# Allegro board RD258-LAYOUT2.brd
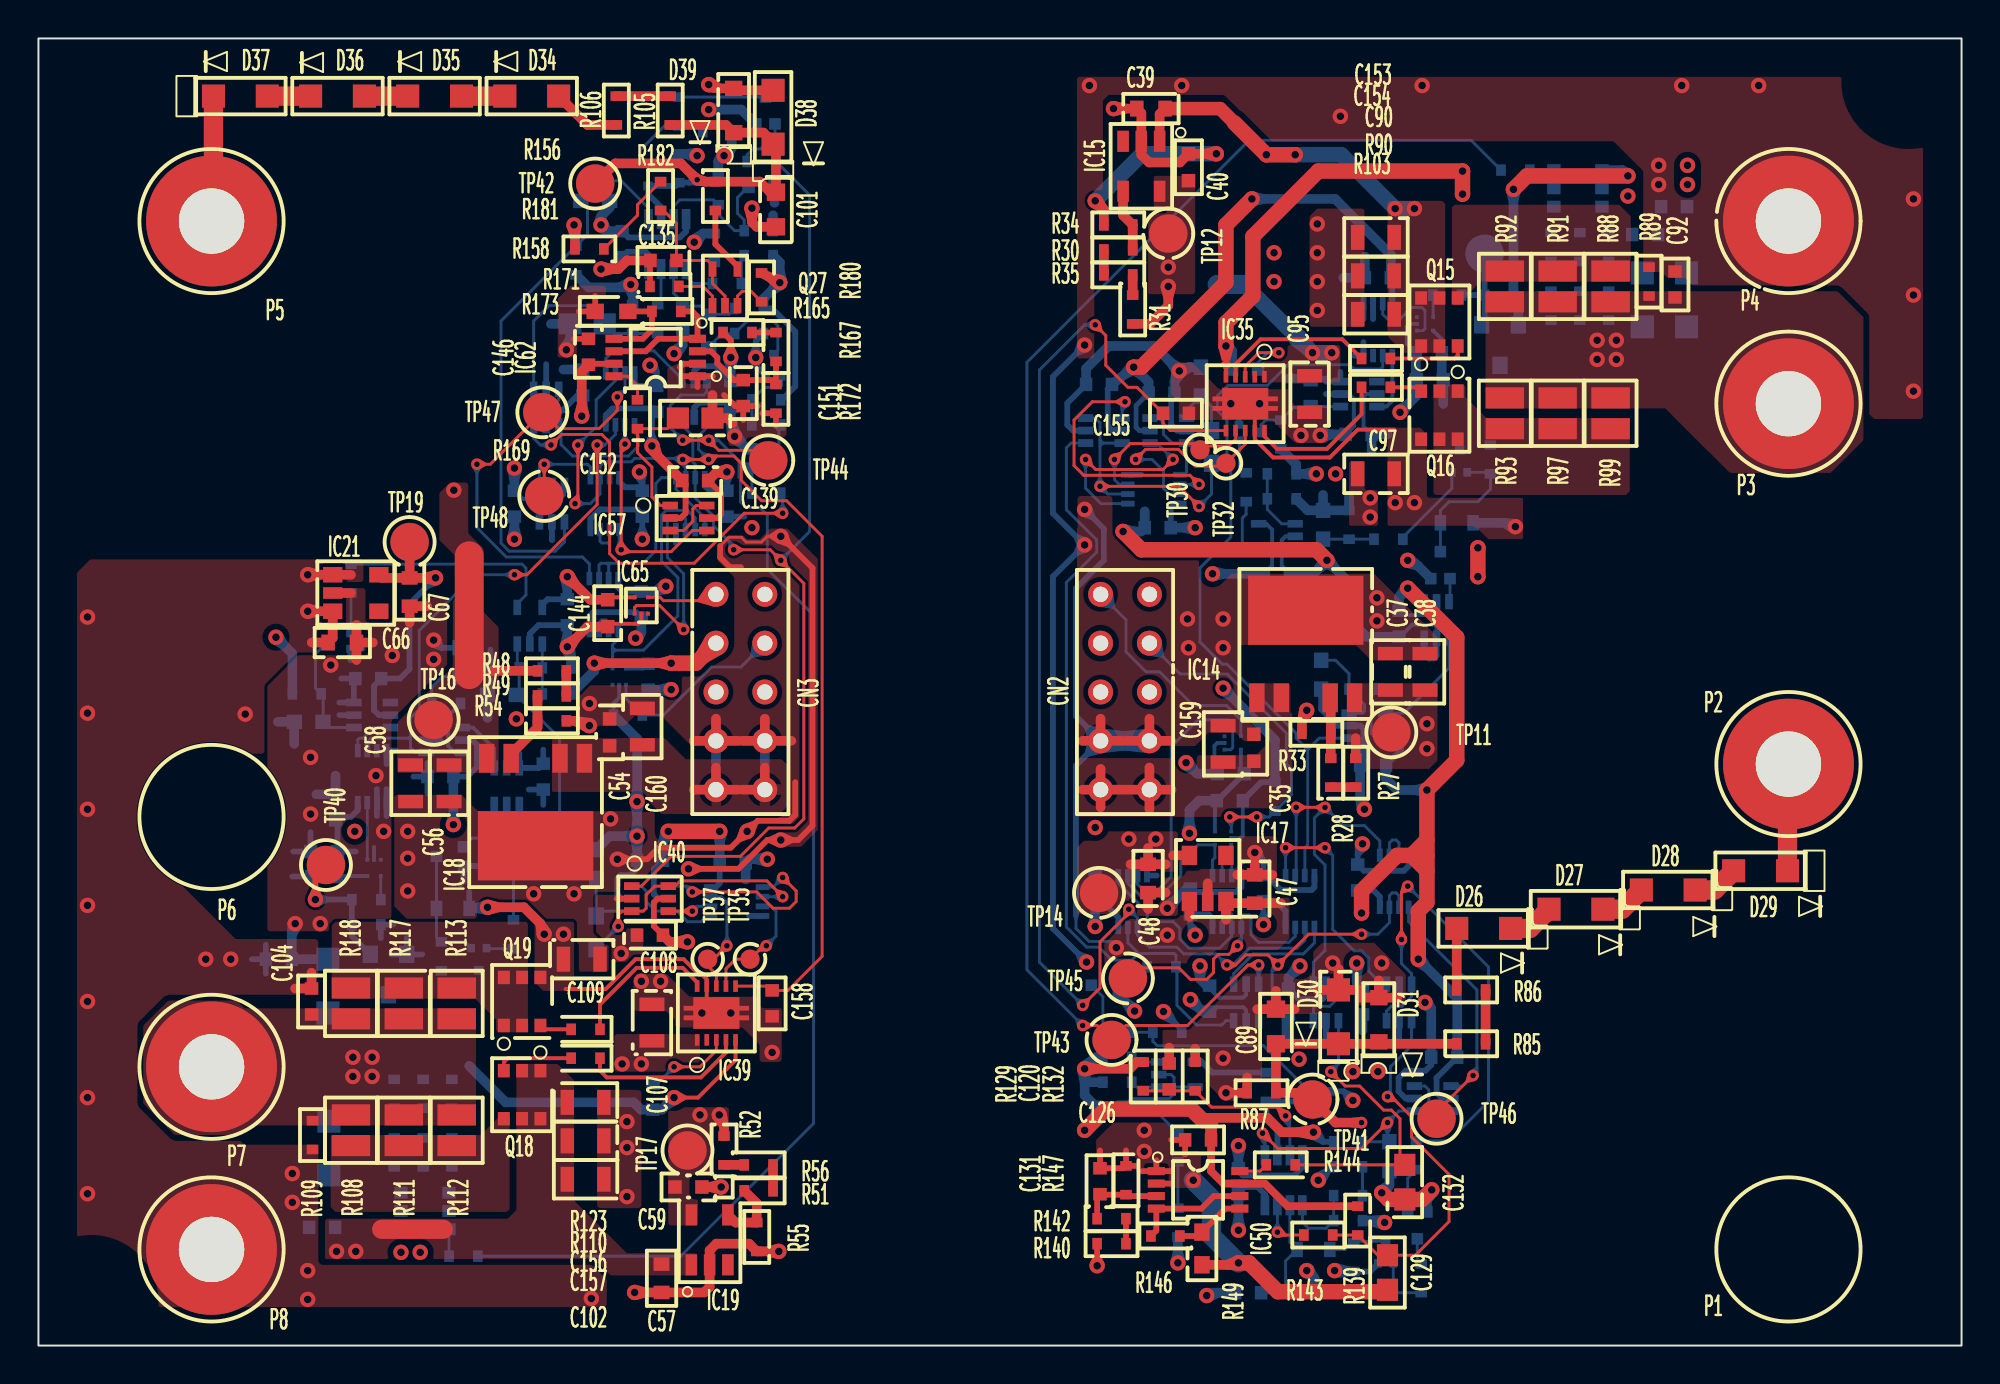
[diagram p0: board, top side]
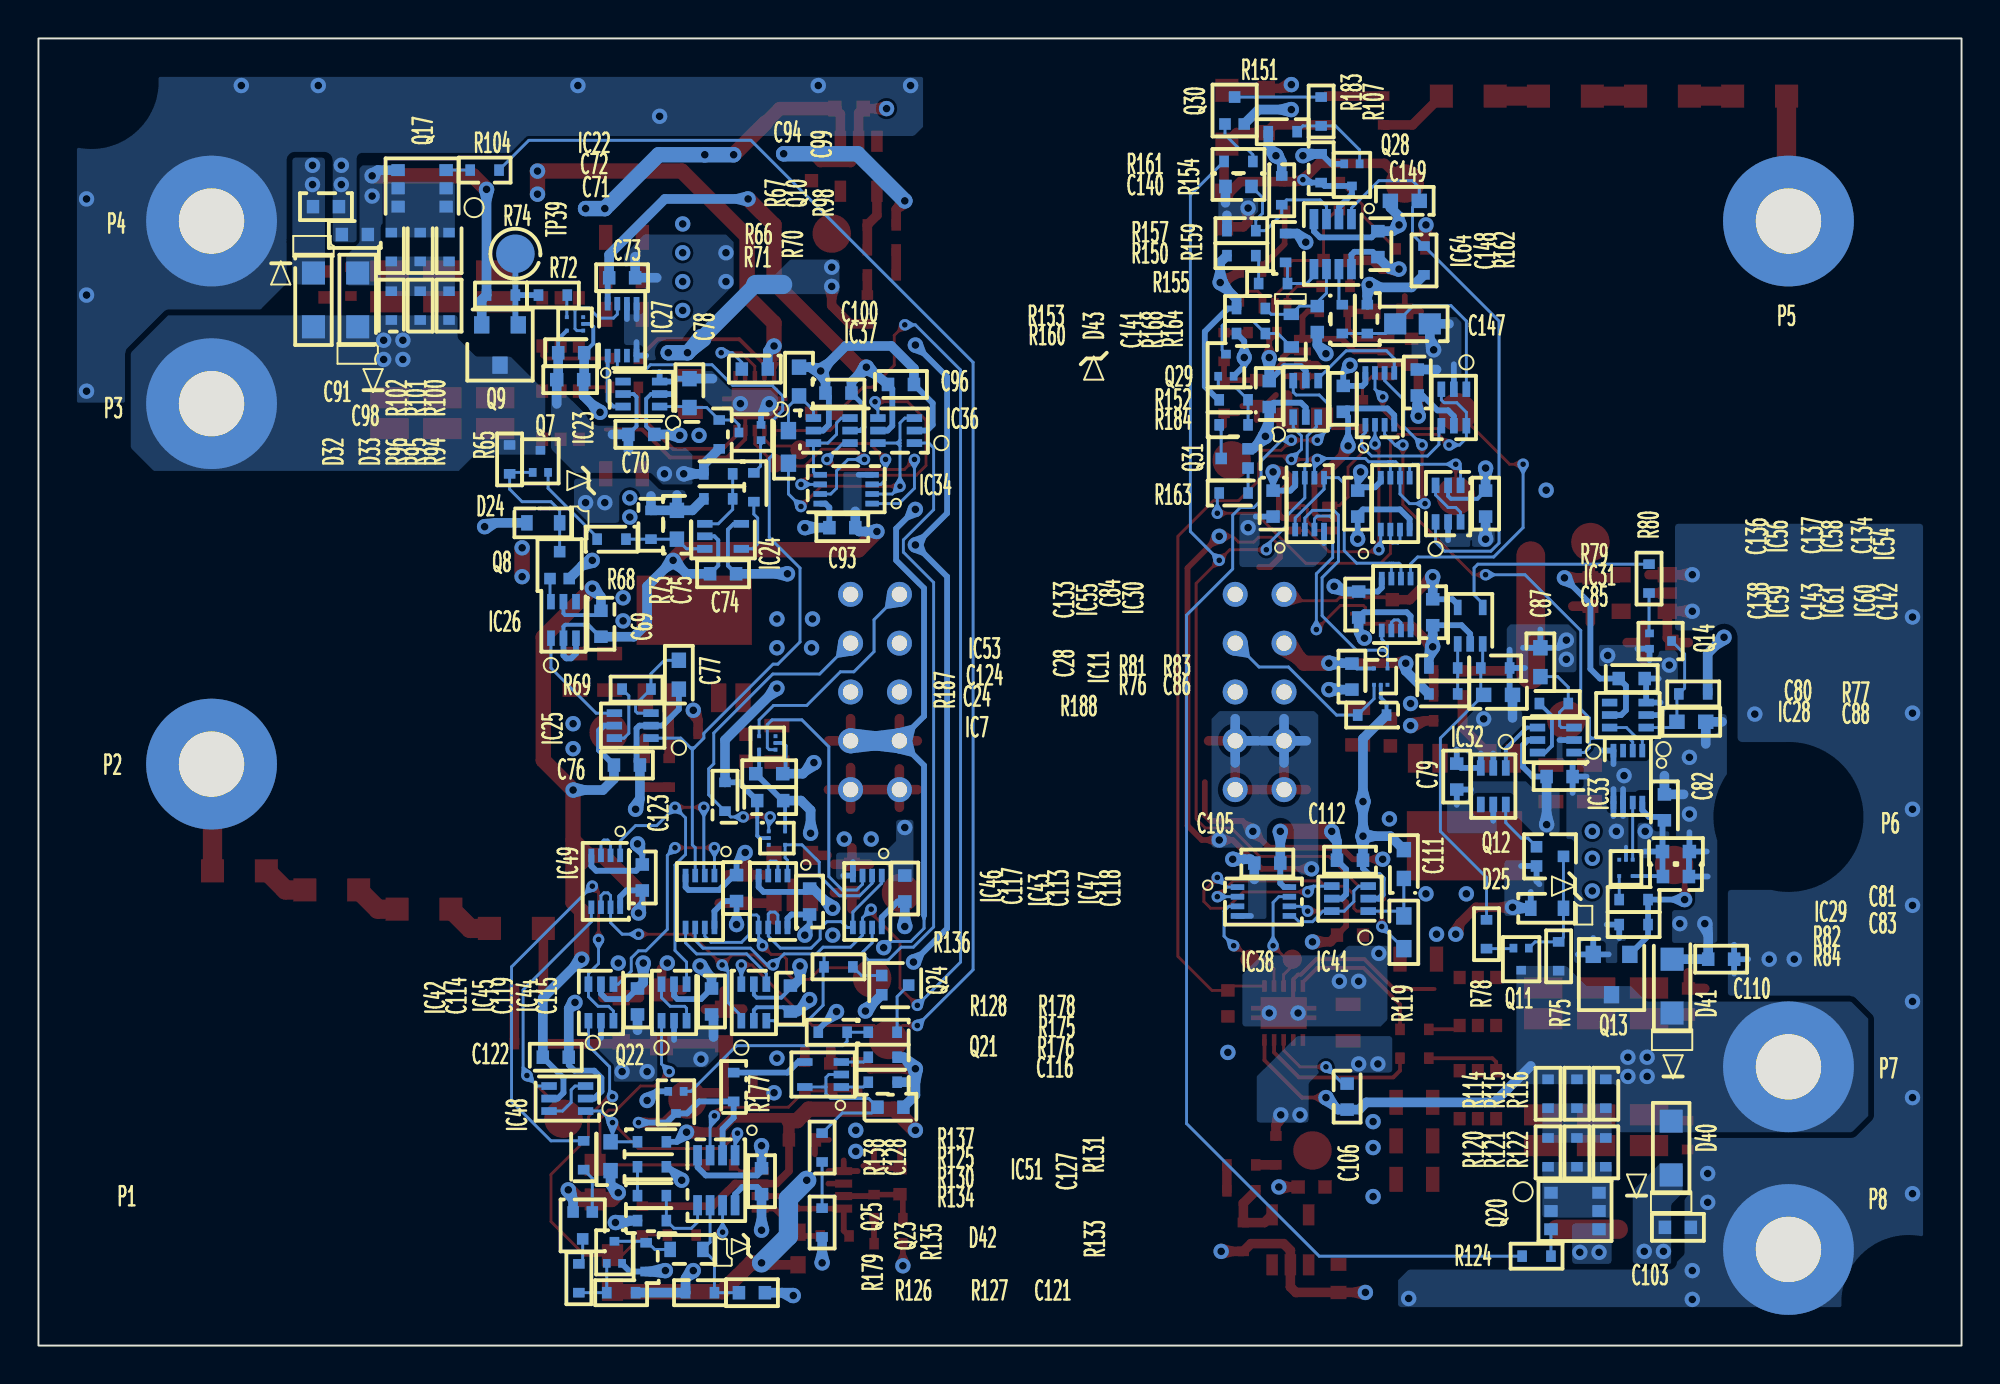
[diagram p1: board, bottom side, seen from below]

Outline 100 x 68 mm; copper layers: TOP, CONDUCTIVE2, CONDUCTIVE3, BOTTOM. Coordinates in mm from the lower left corner of the outline.
Outline path: rectangle 0,0 100,68

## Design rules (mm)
constraint set DEFAULT: 

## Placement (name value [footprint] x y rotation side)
C24  -  [C_CHP_MURATA_L1_6W0_8H0_8A]  61.95 28.35 0 bottom
C28  -  [C_CHP_MURATA_L1_6W0_8H0_8A]  31.7 34.8 270 bottom
C35  -  [C_CHP_TDK_L1_6W0_8H0_8]  63.2 31.1 270 top
C37  -  [C_CHP_MURATA_L2_0W1_25H1_25]  70.3 35.05 270 top
C38  -  [C_CHP_MURATA_L2_0W1_25H1_25]  72.1 35.05 270 top
C39  -  [C_CHP_TYYDN_L1_6W0_8H0_8A]  57.85 64.35 0 top
C40  -  [C_CHP_TDK_L1_6W0_8H0_8]  59.8 61.3 270 top
C47  -  [C_CHP_TYYDN_L1_6W0_8H0_8A]  63.25 23.75 270 top
C48  -  [C_CHP_TYYDN_L1_6W0_8H0_8A]  57.7 24.3 90 top
C54  -  [C_CHP_TDK_L1_6W0_8H0_8]  29.7 31.9 270 top
C56  -  [C_CHP_MURATA_L2_0W1_25H1_25]  21.35 29.25 90 top
C57  -  [C_CHP_TYYDN_L1_6W0_8H0_8A]  32.4 3.5 90 top
C58  -  [C_CHP_MURATA_L2_0W1_25H1_25]  19.35 29.25 90 top
C59  -  [C_CHP_TDK_L1_6W0_8H0_8]  33.8 8.25 180 top
C66  -  [C_CHP_TYYDN_L1_6W0_8H0_8A]  15.8 36.57 180 top
C67  -  [C_CHP_TYYDN_L1_6W0_8H0_8A]  19.3 39.2 90 top
C69  -  [C_CHP_MURATA_L1_6W0_8H0_8A]  70.75 37.55 90 bottom
C70  -  [C_CHP_MURATA_L1_6W0_8H0_8A]  68.65 47.4 0 bottom
C71  -  [C_CHP_TDK_L1_6W0_8H0_8]  72.35 50.25 0 bottom
C72  -  [C_CHP_MURATA_L1_6W0_8H0_8A]  72.3 51.65 0 bottom
C73  -  [C_CHP_MURATA_L1_6W0_8H0_8A]  69.65 55.55 0 bottom
C74  -  [C_CHP_MURATA_L1_6W0_8H0_8A]  64.4 40.15 180 bottom
C75  -  [C_CHP_AVX_L1_6W0_81H0_9]  66.8 42.7 270 bottom
C76  -  [C_CHP_MURATA_L1_6W0_8H0_8A]  69.4 30.2 0 bottom
C77  -  [C_CHP_AVX_L1_6W0_81H0_9]  66.7 34.9 90 bottom
C78  -  [C_CHP_AVX_L1_6W0_81H0_9]  66.15 49.55 270 bottom
C79  -  [C_CHP_MURATA_L1_6W0_8H0_8A]  26.25 29.6 270 bottom
C80  -  [C_CHP_MURATA_L1_6W0_8H0_8A]  17.15 34.7 0 bottom
C81  -  [C_CHP_TDK_L1_6W0_8H0_8]  14.85 25.7 0 bottom
C82  -  [C_CHP_MURATA_L1_6W0_8H0_8A]  15.45 28 270 bottom
C83  -  [C_CHP_MURATA_L1_6W0_8H0_8A]  14.85 24.4 0 bottom
C84  -  [C_CHP_MURATA_L1_6W0_8H0_8A]  27.5 38.15 90 bottom
C85  -  [C_CHP_MURATA_L1_6W0_8H0_8A]  20.9 29.6 0 bottom
C86  -  [C_CHP_AVX_L1_6W0_81H0_9]  24.1 33.85 0 bottom
C87  -  [C_CHP_AVX_L1_6W0_81H0_9]  21.9 35.55 270 bottom
C88  -  [C_CHP_AVX_L1_6W0_81H0_9]  14.05 32.45 0 bottom
C89  -  [C_CHP_AVX_L1_6W0_8H0_9]  64.35 16.6 270 top
C90  -  [C_CHP_MURATA_L2_0W1_25H1_25]  69.55 53.65 0 top
C91  -  [C_CHP_MURATA_L1_6W0_8H0_8A]  85.05 59.25 0 bottom
C92  -  [C_CHP_MURATA_L1_6W0_8H0_8A]  85.1 55.2 90 top
C93  -  [C_CHP_MURATA_L1_6W0_8H0_8A]  58.2 42.55 0 bottom
C94  -  [C_CHP_MURATA_L1_6W0_8H0_8A]  62.75 50.8 0 bottom
C95  -  [C_CHP_MURATA_L2_0W1_25H1_25]  66.1 49.5 90 top
C96  -  [C_CHP_MURATA_L1_6W0_8H0_8A]  55.15 50 0 bottom
C97  -  [C_CHP_MURATA_L2_0W1_25H1_25]  69.55 45.35 180 top
C98  -  [C_CHP_MURATA_L1_6W0_8H0_8A]  83.55 57.8 0 bottom
C99  -  [C_CHP_AVX_L1_6W0_81H0_9]  60.45 50.15 270 bottom
C100  -  [C_CHP_MURATA_L1_6W0_8H0_8A]  58.4 49.55 180 bottom
C101  -  [C_CHP_AVX_L1_6W0_8H0_9]  38.35 59.1 90 top
C102  -  [C_CHP_MURATA_L2_0W1_25H1_25]  28.45 8.65 180 top
C103  -  [C_CHP_MURATA_L1_6W0_8H0_8A]  14.75 6.15 0 bottom
C104  -  [C_CHP_MURATA_L1_6W0_8H0_8A]  14.2 17.9 90 top
C105  -  [C_CHP_MURATA_L1_6W0_8H0_8A]  36.1 25.1 180 bottom
C106  -  [C_CHP_MURATA_L1_6W0_8H0_8A]  31.95 12.95 90 bottom
C107  -  [C_CHP_MURATA_L2_0W1_25H1_25]  31.9 16.8 270 top
C108  -  [C_CHP_MURATA_L1_6W0_8H0_8A]  31.8 21.35 0 top
C109  -  [C_CHP_MURATA_L2_0W1_25H1_25]  28.25 20.1 0 top
C110  -  [C_CHP_MURATA_L1_6W0_8H0_8A]  12.5 20.1 180 bottom
C111  -  [C_CHP_AVX_L1_6W0_81H0_9]  29 25.05 270 bottom
C112  -  [C_CHP_MURATA_L1_6W0_8H0_8A]  31.8 25.25 0 bottom
C113  -  [C_CHP_MURATA_L1_6W0_8H0_8A]  59.9 23.1 270 bottom
C114  -  [C_CHP_MURATA_L1_6W0_8H0_8A]  68.85 17.9 270 bottom
C115  -  [C_CHP_MURATA_L1_6W0_8H0_8A]  60.9 18.05 270 bottom
C116  -  [C_CHP_MURATA_L1_6W0_8H0_8A]  55.7 12.4 180 bottom
C117  -  [C_CHP_MURATA_L1_6W0_8H0_8A]  63.7 23.8 270 bottom
C118  -  [C_CHP_MURATA_L1_6W0_8H0_8A]  54.95 23.77 270 bottom
C119  -  [C_CHP_MURATA_L1_6W0_8H0_8A]  65 17.9 270 bottom
C120  -  [C_CHP_MURATA_L1_6W0_8H0_8A]  58.8 14 270 top
C121  -  [C_CHP_MURATA_L1_6W0_8H0_8A]  62.9 2.75 0 bottom
C122  -  [C_CHP_MURATA_L1_6W0_8H0_8A]  73.1 15 180 bottom
C123  -  [C_CHP_MURATA_L1_6W0_8H0_8A]  68.6 24.35 270 bottom
C124  -  [C_CHP_TDK_L1_6W0_8H0_8]  62 29.75 180 bottom
C126  -  [C_CHP_MURATA_L1_6W0_8H0_8A]  60.3 10.7 0 top
C127  -  [C_CHP_MURATA_L1_6W0_8H0_8A]  62.4 8.55 270 bottom
C128  -  [C_CHP_AVX_L1_6W0_81H0_9]  70.25 9.85 90 bottom
C129  -  [C_CHP_KEMET_L1_6W0_8H0_8]  70.15 3.8 90 top
C131  -  [C_CHP_MURATA_L1_6W0_8H0_8A]  55.2 8.55 270 top
C132  -  [C_CHP_KEMET_L1_6W0_8H0_8]  71.05 8.5 90 top
C133  -  [C_CHP_MURATA_L1_6W0_8H0_8A]  31.35 38.55 90 bottom
C134  -  [C_CHP_MURATA_L1_6W0_8H0_8A]  28.3 50.1 90 bottom
C135  -  [C_CHP_MURATA_L1_6W0_8H0_8A]  32.5 56.45 180 top
C136  -  [C_CHP_MURATA_L1_6W0_8H0_8A]  36 49.5 270 bottom
C137  -  [C_CHP_MURATA_L1_6W0_8H0_8A]  32.15 49.25 90 bottom
C138  -  [C_CHP_MURATA_L1_6W0_8H0_8A]  35.8 43.8 90 bottom
C139  -  [C_CHP_MURATA_L1_6W0_8H0_8A]  34.15 45 180 top
C140  -  [C_CHP_MURATA_L1_6W0_8H0_8A]  37.6 60.3 180 bottom
C141  -  [C_CHP_MURATA_L1_6W0_8H0_8A]  33.5 53.4 90 bottom
C142  -  [C_CHP_MURATA_L1_6W0_8H0_8A]  24.75 43.8 270 bottom
C143  -  [C_CHP_MURATA_L1_6W0_8H0_8A]  31.4 43.8 90 bottom
C144  -  [C_CHP_TDK_L1_6W0_8H0_8]  29.6 38.1 270 top
C146  -  [C_CHP_MURATA_L1_6W0_8H0_8A]  28.6 51.7 270 top
C147  -  [C_CHP_KEMET_L1_6W0_8H0_8]  28.55 53.15 0 bottom
C148  -  [C_CHP_MURATA_L1_6W0_8H0_8A]  30.35 57.3 270 bottom
C149  -  [C_CHP_AVX_L1_6W0_81H0_9]  28.95 59.55 180 bottom
C151  -  [C_CHP_MURATA_L1_6W0_8H0_8A]  36.65 49.55 90 top
C152  -  [C_CHP_KEMET_L1_6W0_8H0_8]  34.15 48.25 180 top
C153  -  [C_CHP_MURATA_L2_0W1_25H1_25]  69.55 57.65 0 top
C154  -  [C_CHP_MURATA_L2_0W1_25H1_25]  69.55 55.65 0 top
C155  -  [C_CHP_MURATA_L1_6W0_8H0_8A]  59.15 48.5 0 top
C156  -  [C_CHP_MURATA_L2_0W1_25H1_25]  28.45 12.65 180 top
C157  -  [C_CHP_MURATA_L2_0W1_25H1_25]  28.45 10.65 180 top
C158  -  [C_CHP_MURATA_L1_6W0_8H0_8A]  38.15 17.8 270 top
C159  -  [C_CHP_MURATA_L2_0W1_25H1_25]  61.6 31.3 270 top
C160  -  [C_CHP_MURATA_L2_0W1_25H1_25]  31.4 32.2 270 top
CN2  -  [PMW_61_5PW]  55.23 28.92 90 top
CN3  -  [PMW_61_5PW]  35.23 28.92 90 top
D24  -  [ZD_SMD_TSB_K_1_A_2_L1_2W0_8H0_6]  73.75 42.8 0 bottom
D25  -  [ZD_SMD_TSB_K_1_A_2_L1_2W0_8H0_6]  21.55 22.75 0 bottom
D26  -  [D_SMD_TSB_K_2_A_1_L2_6W1_6H0_98]  75.15 21.7 180 top
D27  -  [D_SMD_TSB_K_2_A_1_L2_6W1_6H0_98]  79.95 22.7 180 top
D28  -  [D_SMD_TSB_K_2_A_1_L2_6W1_6H0_98]  84.75 23.7 180 top
D29  -  [D_SMD_TSB_K_2_A_1_L2_6W1_6H0_98]  89.55 24.7 180 top
D30  -  [D_SMD_TSB_K_2_A_1_L2_6W1_6H0_98]  67.6 17.1 90 top
D31  -  [D_SMD_TSB_K_2_A_1_L1_7W1_25H0_9]  69.7 16.95 90 top
D32  -  [D_SMD_TSB_K_2_A_1_L2_6W1_6H0_98]  85.7 54.4 270 bottom
D33  -  [D_SMD_TSB_K_2_A_1_L2_6W1_6H0_98]  83.4 54.4 90 bottom
D34  -  [D_SMD_TSB_K_2_A_1_L2_6W1_6H0_98]  25.65 65 0 top
D35  -  [D_SMD_TSB_K_2_A_1_L2_6W1_6H0_98]  20.6 65 0 top
D36  -  [D_SMD_TSB_K_2_A_1_L2_6W1_6H0_98]  15.55 65 0 top
D37  -  [D_SMD_TSB_K_2_A_1_L2_6W1_6H0_98]  10.5 65 0 top
D38  -  [D_SMD_TSB_K_2_A_1_L2_6W1_6H0_98]  38.2 63.9 90 top
D39  -  [D_SMD_TSB_K_2_A_1_L1_7W1_25H0_9]  36.15 64.25 90 top
D40  -  [D_SMD_TSB_K_2_A_1_L2_6W1_6H0_98]  15.1 10.28 90 bottom
D41  -  [D_SMD_TSB_K_2_A_1_L2_6W1_6H0_98]  15.05 18.7 90 bottom
D42  -  [ZD_SMD_TSB_K_1_A_2_L1_2W0_8H0_6]  66.3 5 0 bottom
D43  -  [ZD_SMD_TSB_K_1_A_2_L1_2W0_8H0_6]  34.85 52.8 270 bottom
IC7  -  [IC_SMD_5_TSB_L1_0W0_8H0_48_RCNT]  61.6 26.4 270 bottom
IC11  -  [IC_SMD_5_TSB_L1_0W0_8H0_48_RCNT]  30.2 34.8 180 bottom
IC14  -  [REG_TO_252_5S_A_ABLIC_L6_5W4_7H1_4]  65.9 37 0 top
IC15  -  [IC_SOP_5_TI_L3_05W1_75H1_45]  57.35 61.35 180 top
IC17  -  [IC_SC74A_TSB_L2_9W1_6H1_15_RP0_05]  60.8 24.3 0 top
IC18  -  [REG_TO_252_5S_A_ABLIC_L6_5W4_7H1_4]  25.85 27.25 180 top
IC19  -  [IC_SOP_5_TI_L3_05W1_75H1_45]  34.9 5.5 0 top
IC21  -  [IC_SC74A_TSB_L2_9W1_6H1_15_RP0_05]  16.5 39.15 270 top
IC22  -  [IC_SMD_5_TSB_L1_0W0_8H0_48_RCNT]  72.1 53.15 90 bottom
IC23  -  [IC_SOP_6_TSB_L2_0W1_25H0_95_RP0_05]  68.65 49.5 90 bottom
IC24  -  [IC_SC88A_TSB_L2_0W1_25H0_95_RP0_05]  64.4 42.1 270 bottom
IC25  -  [IC_SOP_6_TSB_L2_0W1_25H0_95_RP0_05]  69.1 32.25 90 bottom
IC26  -  [IC_SOP_6_TSB_L2_0W1_25H0_95_RP0_05]  72.7 37.75 180 bottom
IC27  -  [IC_SOP_8_TSB_L2_0W2_3H0_75_P0_5_RP0_05]  69.65 52.85 180 bottom
IC28  -  [IC_SOP_6_TSB_L2_0W1_25H0_95_RP0_05]  17.35 32.8 90 bottom
IC29  -  [IC_SMD_5_TSB_L1_0W0_8H0_48_RCNT]  17.45 24.85 0 bottom
IC30  -  [IC_SC88A_TSB_L2_0W1_25H0_95_RP0_05]  25.55 37.45 180 bottom
IC31  -  [IC_SOP_6_TSB_L2_0W1_25H0_95_RP0_05]  21.1 31.5 90 bottom
IC32  -  [IC_SOP_6_TSB_L2_0W1_25H0_95_RP0_05]  24.35 29.1 0 bottom
IC33  -  [IC_SOP_8_TSB_L2_0W2_3H0_75_P0_5_RP0_05]  17.35 29.6 0 bottom
IC34  -  [IC_SOP_8_TSB_L2_0W2_3H0_75_P0_5_RP0_05]  58 44.55 90 bottom
IC35  -  [IC_SON_10S1_TI_L3_1W3_1H1_0_RP0_05_2]  62.75 49 180 top
IC36  -  [IC_SOP_6_TSB_L2_0W1_25H0_95_RP0_05]  55.4 47.6 90 bottom
IC37  -  [IC_SOP_6_TSB_L2_0W1_25H0_95_RP0_05]  58.75 47.6 270 bottom
IC38  -  [IC_SOP_8_TSB_L2_0W2_3H0_75_P0_5_RP0_05]  36.3 23.1 270 bottom
IC39  -  [IC_SON_10S1_TI_L3_1W3_1H1_0_RP0_05_2]  35.25 17.3 0 top
IC40  -  [IC_SOP_6_TSB_L2_0W1_25H0_95_RP0_05]  31.8 23.25 270 top
IC41  -  [IC_SOP_6_TSB_L2_0W1_25H0_95_RP0_05]  31.8 23.25 90 bottom
IC42  -  [IC_SOP_6_TSB_L2_0W1_25H0_95_RP0_05]  70.75 17.85 180 bottom
IC43  -  [IC_SOP_8_TSB_L2_0W2_3H0_75_P0_5_RP0_05]  61.8 23.1 0 bottom
IC44  -  [IC_SOP_6_TSB_L2_0W1_25H0_95_RP0_05]  62.8 17.85 180 bottom
IC45  -  [IC_SOP_6_TSB_L2_0W1_25H0_95_RP0_05]  66.95 17.85 180 bottom
IC46  -  [IC_SOP_8_TSB_L2_0W2_3H0_75_P0_5_RP0_05]  65.6 23.1 0 bottom
IC47  -  [IC_SOP_8_TSB_L2_0W2_3H0_75_P0_5_RP0_05]  56.9 23.1 0 bottom
IC48  -  [IC_SOP_6_TSB_L2_0W1_25H0_95_RP0_05]  72.5 12.85 90 bottom
IC49  -  [IC_SOP_8_TSB_L2_0W2_3H0_75_P0_5_RP0_05]  70.5 24.15 0 bottom
IC50  -  [IC_MS8_LINEAR_L3_0W3_0H1_1_P0_65]  60.3 8.1 270 top
IC51  -  [IC_DDF_TI_L2_9W1_6H1_1_P0_65]  64.75 8.6 0 bottom
IC53  -  [IC_SMD_5_TSB_L1_0W0_8H0_48_RCNT]  62.1 31.35 90 bottom
IC54  -  [IC_SOP_6_TSB_L2_0W1_25H0_95_RP0_05]  26.4 48.8 0 bottom
IC55  -  [IC_SOP_8_TSB_L2_0W2_3H0_75_P0_5_RP0_05]  29.4 38.55 180 bottom
IC56  -  [IC_SOP_6_TSB_L2_0W1_25H0_95_RP0_05]  34.1 49.25 180 bottom
IC57  -  [IC_SOP_6_TSB_L2_0W1_25H0_95_RP0_05]  33.8 43.05 270 top
IC58  -  [IC_SOP_8_TSB_L2_0W2_3H0_75_P0_5_RP0_05]  30.25 49.25 180 bottom
IC59  -  [IC_SOP_8_TSB_L2_0W2_3H0_75_P0_5_RP0_05]  33.9 43.8 180 bottom
IC60  -  [IC_SOP_6_TSB_L2_0W1_25H0_95_RP0_05]  26.7 43.8 180 bottom
IC61  -  [IC_SOP_8_TSB_L2_0W2_3H0_75_P0_5_RP0_05]  29.45 43.8 180 bottom
IC62  -  [IC_MS8_LINEAR_L3_0W3_0H1_1_P0_65]  32.1 51.4 90 top
IC64  -  [IC_DDF_TI_L2_9W1_6H1_1_P0_65]  32.7 57.3 0 bottom
IC65  -  [IC_SMD_5_TSB_L1_0W0_8H0_48_RCNT]  31.35 38.5 0 top
NOREF  -  []  91 5 0 top
NOREF#2  -  []  9 27.5 0 top
P2  -  [ITNS_TH3_4_P_C6_8]  91 30.25 0 top
P3  -  [ITNS_TH3_4_P_C6_8]  91 49 0 top
P4  -  [ITNS_TH3_4_P_C6_8]  91 58.5 0 top
P5  -  [ITNS_TH3_4_P_C6_8]  9 58.5 0 top
P7  -  [ITNS_TH3_4_P_C6_8]  9 14.5 0 top
P8  -  [ITNS_TH3_4_P_C6_8]  9 5 0 top
Q7  -  [TR_SMD_3_TSB_B_1_E_2_C_3_L1_2W0_8H0_5]  73.9 46 180 bottom
Q8  -  [FET_SMD_TSB_G_1_S_2_D_3_L1_6W0_8H0_75]  72.9 40.6 180 bottom
Q9  -  [FET_SMD_TSB_L2_9W1_8H0_8]  76 52.05 0 bottom
Q10  -  [TR_SMD_3_TSB_B_1_E_2_C_3_L1_2W0_8H0_5]  63 47.5 90 bottom
Q11  -  [TR_SMD_3_TSB_B_1_E_2_C_3_L1_2W0_8H0_5]  22.9 20.1 0 bottom
Q12  -  [FET_SMD_TSB_G_1_S_2_D_3_L1_6W0_8H0_75]  21.4 25.45 270 bottom
Q13  -  [FET_SMD_TSB_L2_9W1_8H0_8]  18.2 19.3 0 bottom
Q14  -  [TR_SMD_3_TSB_B_1_E_2_C_3_L1_2W0_8H0_5]  15.65 36.65 270 bottom
Q15  -  [FET_SMD_TSB_D_1_2_5_6_G_3_S_4_L2_9W2_2H0_8_RP0_05]  72.85 53.25 0 top
Q16  -  [FET_SMD_TSB_D_1_2_5_6_G_3_S_4_L2_9W2_2H0_8_RP0_05]  72.85 48.4 180 top
Q17  -  [FET_SMD_TSB_D_1_2_5_6_G_3_S_4_L2_9W2_2H0_8_RP0_05]  80.05 60.2 90 bottom
Q18  -  [FET_SMD_TSB_D_1_2_5_6_G_3_S_4_L2_9W2_2H0_8_RP0_05]  25.15 13.05 180 top
Q19  -  [FET_SMD_TSB_D_1_2_5_6_G_3_S_4_L2_9W2_2H0_8_RP0_05]  25.15 17.9 0 top
Q20  -  [FET_SMD_TSB_D_1_2_5_6_G_3_S_4_L2_9W2_2H0_8_RP0_05]  20.1 7 270 bottom
Q21  -  [TR_USV_TSB_L2_0W1_25H1_1]  59.2 14.1 90 bottom
Q22  -  [TR_SMD_3_TSB_B_1_E_2_C_3_L1_2W0_8H0_5]  66.85 12.65 0 bottom
Q23  -  [TR_SMD_3_TSB_B_1_E_2_C_3_L1_2W0_8H0_5]  70.05 4.85 180 bottom
Q24  -  [FET_SMD_TSB_G_1_S_2_D_3_L1_6W0_8H0_75]  55.45 18.75 270 bottom
Q25  -  [FET_SMD_TSB_G_1_S_2_D_3_L1_6W0_8H0_75]  71.7 6.25 0 bottom
Q27  -  [TR_USV_TSB_L2_0W1_25H1_1]  35.7 55.05 0 top
Q28  -  [TR_SMD_3_TSB_B_1_E_2_C_3_L1_2W0_8H0_5]  31.7 60.9 0 bottom
Q29  -  [TR_SMD_3_TSB_B_1_E_2_C_3_L1_2W0_8H0_5]  38.25 51 180 bottom
Q30  -  [FET_SMD_TSB_G_1_S_2_D_3_L1_6W0_8H0_75]  37.8 64.25 180 bottom
Q31  -  [FET_SMD_TSB_G_1_S_2_D_3_L1_6W0_8H0_75]  37.8 46.15 90 bottom
R27  -  [R_CHP_KOA_L1_6W0_8H0_45]  68.5 29.8 90 top
R28  -  [R_CHP_KOA_L1_6W0_8H0_45]  67.2 29.8 270 top
R30  -  [R_CHP_KOA_L1_6W0_8H0_45]  56.15 57 180 top
R31  -  [R_CHP_KOA_L1_6W0_8H0_45]  56.9 53.9 270 top
R33  -  [R_CHP_KOA_L1_6W0_8H0_45]  66.45 31.85 0 top
R34  -  [R_CHP_KOA_L1_6W0_8H0_45]  56.15 58.3 0 top
R35  -  [R_CHP_KOA_L1_6W0_8H0_45]  56.15 55.7 0 top
R48  -  [R_CHP_KOA_L1_6W0_8H0_45]  26.7 35.1 180 top
R49  -  [R_CHP_KOA_L1_6W0_8H0_45]  26.7 33.8 0 top
R51  -  [R_CHP_KOA_L1_6W0_8H0_45]  37.45 8.05 0 top
R52  -  [R_CHP_KOA_L1_6W0_8H0_45]  35.65 10.15 90 top
R54  -  [R_CHP_KOA_L1_6W0_8H0_45]  26.7 32.5 180 top
R55  -  [R_CHP_KOA_L1_6W0_8H0_45]  37.35 5.65 90 top
R56  -  [R_CHP_KOA_L1_6W0_8H0_45]  37.45 9.4 180 top
R65  -  [R_CHP_KOA_L1_6W0_8H0_45]  75.5 46.1 90 bottom
R66  -  [R_CHP_KOA_L1_6W0_8H0_45]  64.65 45.35 0 bottom
R67  -  [R_CHP_KOA_L1_6W0_8H0_45]  64.6 47.4 270 bottom
R68  -  [R_CHP_KOA_L1_6W0_8H0_45]  70.2 41.95 0 bottom
R69  -  [R_CHP_KOA_L1_6W0_8H0_45]  68.9 34.15 180 bottom
R70  -  [R_CHP_KOA_L1_6W0_8H0_45]  62.8 44.65 270 bottom
R71  -  [R_CHP_KOA_L1_6W0_8H0_45]  64.65 44.05 180 bottom
R72  -  [R_CHP_KOA_L1_6W0_8H0_45]  73.25 54.65 0 bottom
R73  -  [R_CHP_KOA_L1_6W0_8H0_45]  68.15 42.7 270 bottom
R74  -  [R_CHP_KOA_L1_6W0_8H0_45]  75.95 54.65 180 bottom
R75  -  [R_CHP_KOA_L1_6W0_8H0_45]  20.95 20.25 270 bottom
R76  -  [R_CHP_KOA_L1_6W0_8H0_45]  26.95 33.9 0 bottom
R77  -  [R_CHP_KOA_L1_6W0_8H0_45]  13.95 33.9 180 bottom
R78  -  [R_CHP_KOA_L1_6W0_8H0_45]  24.7 21.4 270 bottom
R79  -  [R_CHP_KOA_L1_6W0_8H0_45]  21.2 33.4 180 bottom
R80  -  [R_CHP_KOA_L1_6W0_8H0_45]  16.25 39.9 90 bottom
R81  -  [R_CHP_KOA_L1_6W0_8H0_45]  26.95 35.25 180 bottom
R82  -  [R_CHP_KOA_L1_6W0_8H0_45]  17.05 23.2 180 bottom
R83  -  [R_CHP_KOA_L1_6W0_8H0_45]  24.25 35.25 0 bottom
R84  -  [R_CHP_KOA_L1_6W0_8H0_45]  17.05 21.9 180 bottom
R85  -  [R_CHP_KOA_L1_6W0_8H0_45]  74.5 15.7 0 top
R86  -  [R_CHP_KOA_L1_6W0_8H0_45]  74.5 18.5 180 top
R87  -  [R_CHP_KOA_L1_6W0_8H0_45]  63.6 13.15 0 top
R88  -  [R_CHP_ROHM_L2_0W1_2H0_55]  81.75 55.1 180 top
R89  -  [R_CHP_KOA_L1_6W0_8H0_45]  83.75 55.35 90 top
R90  -  [R_CHP_KOA_L1_6W0_8H0_45]  69.55 51.35 0 top
R91  -  [R_CHP_ROHM_L2_0W1_2H0_55]  79 55.1 180 top
R92  -  [R_CHP_ROHM_L2_0W1_2H0_55]  76.25 55.1 180 top
R93  -  [R_CHP_ROHM_L2_0W1_2H0_55]  76.25 48.5 0 top
R94  -  [R_CHP_KOA_L1_6W0_8H0_45]  78.65 54.1 270 bottom
R95  -  [R_CHP_KOA_L1_6W0_8H0_45]  80.15 54.1 270 bottom
R96  -  [R_CHP_KOA_L1_6W0_8H0_45]  81.65 54.1 270 bottom
R97  -  [R_CHP_ROHM_L2_0W1_2H0_55]  79 48.5 0 top
R98  -  [R_CHP_YAGEO_L1_6W0_8H0_45]  61 46.75 90 bottom
R99  -  [R_CHP_ROHM_L2_0W1_2H0_55]  81.75 48.5 0 top
R100  -  [R_CHP_KOA_L1_6W0_8H0_45]  78.65 57.15 270 bottom
R101  -  [R_CHP_KOA_L1_6W0_8H0_45]  80.15 57.15 270 bottom
R102  -  [R_CHP_KOA_L1_6W0_8H0_45]  81.65 57.15 270 bottom
R103  -  [R_CHP_KOA_L1_6W0_8H0_45]  69.55 49.85 0 top
R104  -  [R_CHP_KOA_L1_6W0_8H0_45]  76.8 61.15 0 bottom
R105  -  [R_CHP_KOA_L1_6W0_8H0_45]  32.85 64.25 90 top
R106  -  [R_CHP_KOA_L1_6W0_8H0_45]  30.05 64.25 270 top
R107  -  [R_CHP_KOA_L1_6W0_8H0_45]  33.3 61.25 270 bottom
R108  -  [R_CHP_ROHM_L2_0W1_2H0_55]  16.25 11.2 0 top
R109  -  [R_CHP_KOA_L1_6W0_8H0_45]  14.25 10.95 270 top
R110  -  [R_CHP_KOA_L1_6W0_8H0_45]  28.45 14.95 180 top
R111  -  [R_CHP_ROHM_L2_0W1_2H0_55]  19 11.2 0 top
R112  -  [R_CHP_ROHM_L2_0W1_2H0_55]  21.75 11.2 0 top
R113  -  [R_CHP_ROHM_L2_0W1_2H0_55]  21.75 17.8 180 top
R114  -  [R_CHP_KOA_L1_6W0_8H0_45]  21.5 13.1 90 bottom
R115  -  [R_CHP_KOA_L1_6W0_8H0_45]  20 13.1 90 bottom
R116  -  [R_CHP_KOA_L1_6W0_8H0_45]  18.5 13.1 90 bottom
R117  -  [R_CHP_ROHM_L2_0W1_2H0_55]  19 17.8 180 top
R118  -  [R_CHP_ROHM_L2_0W1_2H0_55]  16.25 17.8 180 top
R119  -  [R_CHP_YAGEO_L1_6W0_8H0_45]  29 21.5 90 bottom
R120  -  [R_CHP_KOA_L1_6W0_8H0_45]  21.5 10.05 90 bottom
R121  -  [R_CHP_KOA_L1_6W0_8H0_45]  20 10.05 90 bottom
R122  -  [R_CHP_KOA_L1_6W0_8H0_45]  18.5 10.05 90 bottom
R123  -  [R_CHP_KOA_L1_6W0_8H0_45]  28.45 16.45 180 top
R124  -  [R_CHP_KOA_L1_6W0_8H0_45]  22.1 4.65 180 bottom
R125  -  [R_CHP_KOA_L1_6W0_8H0_45]  68.1 9.3 180 bottom
R126  -  [R_CHP_KOA_L1_6W0_8H0_45]  69.7 2.75 180 bottom
R127  -  [R_CHP_KOA_L1_6W0_8H0_45]  65.6 2.75 0 bottom
R128  -  [R_CHP_KOA_L1_6W0_8H0_45]  58.7 16.3 0 bottom
R129  -  [R_CHP_KOA_L1_6W0_8H0_45]  57.45 14 90 top
R130  -  [R_CHP_KOA_L1_6W0_8H0_45]  68.1 7.8 0 bottom
R131  -  [R_CHP_KOA_L1_6W0_8H0_45]  59.25 10.3 90 bottom
R132  -  [R_CHP_KOA_L1_6W0_8H0_45]  60.15 14 270 top
R133  -  [R_CHP_KOA_L1_6W0_8H0_45]  59.25 6.4 90 bottom
R134  -  [R_CHP_KOA_L1_6W0_8H0_45]  68.1 6.5 180 bottom
R135  -  [R_CHP_KOA_L1_6W0_8H0_45]  68.4 4.6 90 bottom
R136  -  [R_CHP_KOA_L1_6W0_8H0_45]  58.4 19.7 0 bottom
R137  -  [R_CHP_KOA_L1_6W0_8H0_45]  68.1 10.6 180 bottom
R138  -  [R_CHP_KOA_L1_6W0_8H0_45]  71.65 9.9 90 bottom
R139  -  [R_CHP_KOA_L1_6W0_8H0_45]  68.6 6.5 90 top
R140  -  [R_CHP_KOA_L1_6W0_8H0_45]  55.8 5.3 180 top
R142  -  [R_CHP_KOA_L1_6W0_8H0_45]  55.8 6.6 0 top
R143  -  [R_CHP_KOA_L1_6W0_8H0_45]  66.55 5.75 180 top
R144  -  [R_CHP_KOA_L1_6W0_8H0_45]  64.6 9.4 180 top
R146  -  [R_CHP_KOA_L1_6W0_8H0_45]  58.6 5.7 180 top
R147  -  [R_CHP_KOA_L1_6W0_8H0_45]  56.55 8.6 270 top
R149  -  [R_CHP_YAGEO_L1_6W0_8H0_45]  60.5 5.05 90 top
R150  -  [R_CHP_KOA_L1_6W0_8H0_45]  37.45 56.7 0 bottom
R151  -  [R_CHP_KOA_L1_6W0_8H0_45]  35.3 63.15 0 bottom
R152  -  [R_CHP_KOA_L1_6W0_8H0_45]  37.85 49.2 0 bottom
R153  -  [R_CHP_KOA_L1_6W0_8H0_45]  36.95 53.95 0 bottom
R154  -  [R_CHP_KOA_L1_6W0_8H0_45]  35.35 60.1 90 bottom
R155  -  [R_CHP_KOA_L1_6W0_8H0_45]  35.8 55.25 0 bottom
R156  -  [R_CHP_KOA_L1_6W0_8H0_45]  32.35 59.8 270 top
R157  -  [R_CHP_KOA_L1_6W0_8H0_45]  37.45 58 180 bottom
R158  -  [R_CHP_KOA_L1_6W0_8H0_45]  28.65 57.05 0 top
R159  -  [R_CHP_KOA_L1_6W0_8H0_45]  35.15 57.1 270 bottom
R160  -  [R_CHP_KOA_L1_6W0_8H0_45]  36.95 52.65 180 bottom
R161  -  [R_CHP_KOA_L1_6W0_8H0_45]  37.6 61.6 0 bottom
R162  -  [R_CHP_KOA_L1_6W0_8H0_45]  27.95 56.45 270 bottom
R163  -  [R_CHP_KOA_L1_6W0_8H0_45]  37.85 44.35 0 bottom
R164  -  [R_CHP_KOA_L1_6W0_8H0_45]  30.9 53.4 90 bottom
R165  -  [R_CHP_KOA_L1_6W0_8H0_45]  36.35 52.7 180 top
R167  -  [R_CHP_KOA_L1_6W0_8H0_45]  38.35 51.95 90 top
R168  -  [R_CHP_KOA_L1_6W0_8H0_45]  32.2 53.4 90 bottom
R169  -  [R_CHP_KOA_L1_6W0_8H0_45]  31.15 48.45 90 top
R171  -  [R_CHP_KOA_L1_6W0_8H0_45]  32.65 53.8 0 top
R172  -  [R_CHP_KOA_L1_6W0_8H0_45]  38.35 49.25 90 top
R173  -  [R_CHP_YAGEO_L1_6W0_8H0_45]  29.8 53.8 0 top
R175  -  [R_CHP_KOA_L1_6W0_8H0_45]  56.1 15 180 bottom
R176  -  [R_CHP_KOA_L1_6W0_8H0_45]  56.1 13.7 180 bottom
R177  -  [R_CHP_KOA_L1_6W0_8H0_45]  63.85 13.45 90 bottom
R178  -  [R_CHP_KOA_L1_6W0_8H0_45]  56.1 16.3 0 bottom
R179  -  [R_CHP_KOA_L1_6W0_8H0_45]  71.9 3.5 270 bottom
R180  -  [R_CHP_KOA_L1_6W0_8H0_45]  37.6 55.05 90 top
R181  -  [R_CHP_KOA_L1_6W0_8H0_45]  32.55 55.1 180 top
R182  -  [R_CHP_KOA_L1_6W0_8H0_45]  35.2 59.8 270 top
R183  -  [R_CHP_KOA_L1_6W0_8H0_45]  33.3 64.2 270 bottom
R184  -  [R_CHP_KOA_L1_6W0_8H0_45]  37.85 47.9 180 bottom
R187  -  [R_CHP_KOA_L1_6W0_8H0_45]  64.3 28.55 270 bottom
R188  -  [R_CHP_KOA_L1_6W0_8H0_45]  30.65 32.8 0 bottom
TP11  -  [TPAD_P_C2_0_RP0_05_MN]  70.35 31.9 0 top
TP12  -  [TPAD_P_C2_0_RP0_05_MN]  58.75 57.85 0 top
TP14  -  [TPAD_P_C2_0_RP0_05_MN]  55.15 23.55 270 top
TP16  -  [TPAD_P_C2_0_RP0_05_MN]  20.55 32.55 0 top
TP17  -  [TPAD_P_C2_0_RP0_05_MN]  33.75 10.15 270 top
TP19  -  [TPAD_P_C2_0_RP0_05_MN]  19.3 41.8 90 top
TP30  -  [TPAD_P_C1_0_RP0_05_MN]  60.4 46.6 180 top
TP32  -  [TPAD_P_C1_0_RP0_05_MN]  61.75 45.9 180 top
TP35  -  [TPAD_P_C1_0_RP0_05_MN]  37 20.1 270 top
TP37  -  [TPAD_P_C1_0_RP0_05_MN]  34.8 20.1 270 top
TP39  -  [TPAD_P_C2_0_RP0_05_MN]  75.2 56.8 180 bottom
TP40  -  [TPAD_P_C2_0_RP0_05_MN]  14.95 25 180 top
TP41  -  [TPAD_P_C2_0_RP0_05_MN]  66.25 12.8 0 top
TP42  -  [TPAD_P_C2_0_RP0_05_MN]  28.95 60.45 0 top
TP43  -  [TPAD_P_C2_0_RP0_05_MN]  55.8 15.9 0 top
TP44  -  [TPAD_P_C2_0_RP0_05_MN]  37.95 46.05 0 top
TP45  -  [TPAD_P_C2_0_RP0_05_MN]  56.65 19.1 0 top
TP46  -  [TPAD_P_C2_0_RP0_05_MN]  72.7 11.8 0 top
TP47  -  [TPAD_P_C2_0_RP0_05_MN]  26.2 48.55 0 top
TP48  -  [TPAD_P_C2_0_RP0_05_MN]  26.3 44.2 0 top

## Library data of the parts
C24 C28 C69 C70 C72-C74 C76 C79 C80 C82-C85 C91-C94 C96 C98 C100 C103-C106 C108 C110 C112-C115 C117-C119 C122 C123 C126 C127 C133 C134 C136-C139 C142 C143 C146 C148 = GCJ188R71H104KA12D
C35 C40 C54 C59 C71 C81 C124 C144 = C1608X5R1H105K080DB
C37 C38 C56 C58 C95 C107 C159 C160 = GRM21BZ71H475KE15L
C39 C47 C48 C57 C66 C67 = MSASU168SB7474KTNB25
C75 C77 C78 C86-C88 = 06035C680KAT2A
C89 C101 = KGM15ACG2A121KT: alternate symbols: (C89_C_CHP_AVX_L1_6W0_8H0_9,C101_C_CHP_AVX_L1_6W0_8H0_9)
C90 C97 C102 C109 C153 C154 C156 C157 = GRM21BR61H106KE43L
C99 C111 = 06035A200KAT2A
C116 C120 C121 C131 C135 C140 C141 C151 = GCD188R71H103KA01D
C128 C149 = 06035C100KAT2A
C129 C132 C147 C152 = C0603C102K5RACTU
C155 C158 = GCM188R71H102KA37D
CN2 CN3 = PMW-61-5PW: alternate symbols: (CN2_PMW_61_5PW,CN3_PMW_61_5PW)
D24 D25 D42 D43 = CEZ5V6,L3F
D26-D29 D34-D37 = CRF03A,LQ(M
D30 D38 = CRZ10(T5L,TEM,Q)
D31 D39 = CUS05F30,H3F(T
D32 D33 D40 D41 = CRS04(TE85L,Q,M)
IC7 IC11 IC22 IC29 IC53 IC65 = TC7SZ04AFS,L3J
IC14 IC18 = S1213B00HV5T2U7
IC15 IC19 = TLV709A01DBVR
IC17 IC21 = TCR1HF50B,LM(CT
IC23 IC25 IC26 IC28 IC31 IC32 IC36 IC37 IC40-IC42 IC44 IC45 IC48 IC54 IC56 IC57 IC60 = TC7PZ14FU,LJ(CT
IC24 IC30 = TC75S57FU(TE85L,F)
IC27 IC33 IC43 IC49 IC55 IC61 = TC7WZ00FK,LJ(CT
IC34 IC38 IC46 IC47 IC58 IC59 = TC7WZ08FK,LJ(CT
IC35 IC39 = UCC27301ADRCR
IC50 IC62 = LTC1440IMS8
IC51 IC64 = LM393BIDDFR
P2-P5 P7 P8 = ITNS-TH3.4-P_C6.8
Q7 Q10 Q11 Q14 Q22 Q23 Q28 Q29 = 2SC5658T2LR
Q8 Q12 Q24 Q25 Q30 Q31 = SSM3K15AFS,LF(T
Q9 Q13 = SSM3K318R,LF(T
Q15-Q20 = SSM6K804R,LF
Q21 Q27 = HN4A56JU
R27 R48 = RK73H1JTTD2003F
R28 R49 = RK73H1JTTD2001F
R30 R34 R51 R55 = RK73H1JTTD1004F
R31 R52 = RK73H1JTTD4704F
R33 R54 = RK73H1JTTD2002F
R35 R56 = RK73H1JTTD3304F
R65 R73-R75 R83 R84 R89 R109 = RK73B1JTTD103J
R66 R69 R71 R76 R79 R81 = RK73B1JTTD512J
R67 R70 R77 R80 = RK73B1JTTD473J
R68 R78 = RK73B1JTTD471J
R72 R82 R94-R96 R100-R102 R114-R116 R120-R122 = RK73B1JTTD100J
R85 R105 = RK73H1JTTD2200F: alternate symbols: (R105_R_CHP_KOA_L1_6W0_8H0_45,R85_R_CHP_KOA_L1_6W0_8H0_45)
R86 R106 = RK73H1JTTD1101F: alternate symbols: (R106_R_CHP_KOA_L1_6W0_8H0_45,R86_R_CHP_KOA_L1_6W0_8H0_45)
R87 R90 R103 R107 R110 R123 R177 R182 = RK73Z1JTTD: alternate symbols: (T:R_CHP_KOA_L1_6W0_8H0_45,R182_R_CHP_KOA_L1_6W0_8H0_45;B:R_CHP_KOA_L1_6W0_8H0_45,R177_R_CHP_KOA_L1_6W0_8H0_45)
R88 R91 R92 R108 R111 R112 = LTR10EZPF4R70
R93 R97 R99 R113 R117 R118 = LTR10EZPF11R0
R98 R119 = RT0603BRC07500RL
R104 R124 = RK73H1JTTD20R0F
R125 R150 = RK73H1JTTD4302F
R126 R128 R137 R139 R151 R152 R162 R164 = RK73B1JTTD303J
R127 R153 R187 R188 = RK73H1JTTD1003F
R129 R154 = RK73H1JTTD8201F
R130 R155 = RK73H1JTTD2201F
R131 R136 R138 R143 R156 R161 R163 R168 R178 R179 R183 R184 = RK73H1JTTD1001F: alternate symbols: (T:R_CHP_KOA_L1_6W0_8H0_45,R156_R_CHP_KOA_L1_6W0_8H0_45;B:R_CHP_KOA_L1_6W0_8H0_45,R131_R_CHP_KOA_L1_6W0_8H0_45)
R132 R157 = RK73H1JTTD1202F
R133 R158 = RK73H1JTTD1002F: alternate symbols: (T:R_CHP_KOA_L1_6W0_8H0_45,R158_R_CHP_KOA_L1_6W0_8H0_45;B:R_CHP_KOA_L1_6W0_8H0_45,R133_R_CHP_KOA_L1_6W0_8H0_45)
R134 R140 R159 R165 = RK73H1JTTD2702F
R135 R160 = RK73H1JTTD3301F
R142 R167 = RK73H1JTTD3001F
R144 R169 = RK73B1JTTD472J
R146 R171 = RK73H1JTTD1502F
R147 R172 = RK73H1JTTD1802F
R149 R173 = RC0603FR-072M4L
R175 R176 R180 R181 = RK73B1JTTD221J
TP11 TP12 TP14 TP16 TP17 TP19 TP39-TP48 = TPAD-P_C2.0-RP0.05-MN
TP30 TP32 TP35 TP37 = TPAD-P_C1.0-RP0.05-MN

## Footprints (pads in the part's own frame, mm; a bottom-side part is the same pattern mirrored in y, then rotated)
C_CHP_AVX_L1_6W0_8H0_9
  rect 0.9x0.95 smd: 1(-0.9,0) 2(0.9,0)
C_CHP_AVX_L1_6W0_81H0_9
  rect 0.8x0.75 smd: 1(-0.75,0) 2(0.75,0)
C_CHP_KEMET_L1_6W0_8H0_8
  rect 1.15x1.1 smd: 1(-0.9,0) 2(0.9,0)
C_CHP_MURATA_L1_6W0_8H0_8A
  rect 0.65x0.7 smd: 1(-0.675,0) 2(0.675,0)
C_CHP_MURATA_L2_0W1_25H1_25
  rect 0.7x1.3 smd: 1(-0.95,0) 2(0.95,0)
C_CHP_TDK_L1_6W0_8H0_8
  rect 0.7x0.7 smd: 1(-0.7,0) 2(0.7,0)
C_CHP_TYYDN_L1_6W0_8H0_8A
  rect 0.7x0.825 smd: 1(-0.738,0) 2(0.738,0)
D_SMD_TSB_K_2_A_1_L1_7W1_25H0_9
  rect 0.8x0.9 smd: 1(1.15,0) 2(-1.15,0)
D_SMD_TSB_K_2_A_1_L2_6W1_6H0_98
  rect 1.2x1.2 smd: 1(1.4,0) 2(-1.4,0)
FET_SMD_TSB_D_1_2_5_6_G_3_S_4_L2_9W2_2H0_8_RP0_05
  rect 0.62x0.7 smd: 1(-0.95,-1.25) 2(0,-1.25) 3(0.95,-1.25) 4(0.95,1.25) 5(0,1.25) 6(-0.95,1.25)
FET_SMD_TSB_G_1_S_2_D_3_L1_6W0_8H0_75
  rect 0.6x0.6 smd: 1(-0.5,-0.7) 2(0.5,-0.7) 3(0,0.7)
FET_SMD_TSB_L2_9W1_8H0_8
  rect 0.8x0.9 smd: 1(-0.95,-1.05) 2(0.95,-1.05) 3(0,1.05)
IC_DDF_TI_L2_9W1_6H1_1_P0_65
  rect 0.45x1.05 smd: 1(-0.975,-1.3) 2(-0.325,-1.3) 3(0.325,-1.3) 4(0.975,-1.3) 5(0.975,1.3) 6(0.325,1.3) 7(-0.325,1.3) 8(-0.975,1.3)
IC_MS8_LINEAR_L3_0W3_0H1_1_P0_65
  rect 0.42x0.889 smd: 1(-0.975,-2.171) 2(-0.325,-2.171) 3(0.325,-2.171) 4(0.975,-2.171) 5(0.975,2.171) 6(0.325,2.171) 7(-0.325,2.171) 8(-0.975,2.171)
IC_SC74A_TSB_L2_9W1_6H1_15_RP0_05
  rect 0.8x1 smd: 1(-0.95,-1.2) 3(0.95,-1.2) 4(0.95,1.2) 5(-0.95,1.2)
  rect 0.6x1 smd: 2(0,-1.2)
IC_SC88A_TSB_L2_0W1_25H0_95_RP0_05
  rect 0.4x0.8 smd: 1(-0.65,-0.95) 2(0,-0.95) 3(0.65,-0.95) 4(0.65,0.95) 5(-0.65,0.95)
IC_SMD_5_TSB_L1_0W0_8H0_48_RCNT
  rect 0.2x0.2 smd: 1(-0.35,-0.425) 2(0,-0.425) 3(0.35,-0.425) 4(0.35,0.425) 5(-0.35,0.425)
IC_SON_10S1_TI_L3_1W3_1H1_0_RP0_05_2
  rect 0.24x0.6 smd: 1(-1,-1.4) 2(-0.5,-1.4) 3(0,-1.4) 4(0.5,-1.4) 5(1,-1.4) 6(1,1.4) 7(0.5,1.4) 8(0,1.4) 9(-0.5,1.4) 10(-1,1.4)
  custom 0.412x0.412 smd: 11(0,0)
IC_SOP_5_TI_L3_05W1_75H1_45
  rect 0.6x1.1 smd: 1(-0.95,-1.3) 2(0,-1.3) 3(0.95,-1.3) 4(0.95,1.3) 5(-0.95,1.3)
IC_SOP_6_TSB_L2_0W1_25H0_95_RP0_05
  rect 0.4x0.8 smd: 1(-0.65,-0.95) 2(0,-0.95) 3(0.65,-0.95) 4(0.65,0.95) 5(0,0.95) 6(-0.65,0.95)
IC_SOP_8_TSB_L2_0W2_3H0_75_P0_5_RP0_05
  rect 0.3x0.7 smd: 1(-0.75,-1.35) 2(-0.25,-1.35) 3(0.25,-1.35) 4(0.75,-1.35) 5(0.75,1.35) 6(0.25,1.35) 7(-0.25,1.35) 8(-0.75,1.35)
ITNS_TH3_4_P_C6_8
  round 6.8 hole 3.4: 1(0,0)
PMW_61_5PW
  round 1.3 hole 0.8: 1(0,0) 2(0,-2.54) 3(2.54,0) 4(2.54,-2.54) 5(5.08,0) 6(5.08,-2.54) 7(7.62,0) 8(7.62,-2.54) 9(10.16,0) 10(10.16,-2.54)
R_CHP_KOA_L1_6W0_8H0_45
  rect 0.5x0.6 smd: 1(-0.75,0) 2(0.75,0)
R_CHP_ROHM_L2_0W1_2H0_55
  rect 2x1.1 smd: 1(0,-0.8) 2(0,0.8)
R_CHP_YAGEO_L1_6W0_8H0_45
  rect 0.9x0.8 smd: 1(-0.85,0) 2(0.85,0)
REG_TO_252_5S_A_ABLIC_L6_5W4_7H1_4
  rect 0.8x1.5 smd: 1(-2.54,-3.3) 2(-1.27,-3.3) 4(1.27,-3.3) 5(2.54,-3.3)
  rect 6x3.6 smd: 3(0,1.25)
TPAD_P_C1_0_RP0_05_MN
  round 1 smd: 1(0,0)
TPAD_P_C2_0_RP0_05_MN
  round 2 smd: 1(0,0)
TR_SMD_3_TSB_B_1_E_2_C_3_L1_2W0_8H0_5
  rect 0.4x0.45 smd: 1(-0.4,-0.575) 2(0.4,-0.575)
  rect 0.5x0.45 smd: 3(0,0.575)
TR_USV_TSB_L2_0W1_25H1_1
  rect 0.4x0.8 smd: 1(-0.65,-0.95) 2(0,-0.95) 3(0.65,-0.95) 4(0.65,0.95) 5(-0.65,0.95)
ZD_SMD_TSB_K_1_A_2_L1_2W0_8H0_6
  rect 0.6x0.8 smd: 1(-0.85,0) 2(0.85,0)

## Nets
VCC20_A: C37.2 C38.2 C39.2 C90.2 C91.2 C116.2 C127.2 C153.2 C154.2 D32.2 IC14.5 IC15.1 IC51.8 Q15.1 Q15.2 Q15.5 Q15.6 R27.2 R125.2 R126.2 R127.2 R128.2 R129.2 R175.2 R176.2 TP11.1
VCC20_B: C56.2 C57.2 C58.2 C102.2 C103.2 C135.2 C148.2 C156.2 C157.2 D40.2 IC18.5 IC19.1 IC64.8 Q18.1 Q18.2 Q18.5 Q18.6 R48.2 R150.2 R151.2 R152.2 R153.2 R154.2 R180.2 R181.2 TP16.1
VEE_A: C24.2 C39.1 C40.1 C47.1 C48.1 C69.1 C70.1 C71.1 C72.1 C73.1 C74.1 C75.1 C76.1 C77.1 C78.1 C93.1 C95.1 C96.1 C97.1 C98.1 C99.1 C100.1 C113.1 C114.2 C115.2 C117.1 C118.1 C119.2 C122.2 C123.1 C124.2 C126.1 C127.1 C128.1 C129.1 C131.1 C132.1 C155.2 CN2.5 CN2.6 D24.2 D33.1 IC7.2 IC15.2 IC17.2 IC22.2 IC23.2 IC23.3 IC24.2 IC25.2 IC26.2 IC26.3 IC27.4 IC27.5 IC27.6 IC34.4 IC35.9 IC35.11 IC36.2 IC37.2 IC42.2 IC43.4 IC44.2 IC45.2 IC46.4 IC47.4 IC48.2 IC49.4 IC50.1 IC50.2 IC51.4 IC53.2 Q8.2 Q9.2 Q10.2 Q16.4 Q17.4 Q24.2 Q25.2 R34.1 R71.1 R73.1 R74.1 R147.1 R149.1 R187.1
VEE_B: C28.2 C57.1 C59.1 C66.1 C67.1 C79.1 C80.1 C81.1 C82.1 C83.1 C84.1 C85.1 C86.1 C87.1 C88.1 C105.1 C107.1 C108.1 C109.1 C110.1 C111.1 C112.1 C133.1 C134.2 C136.2 C137.1 C138.1 C139.2 C142.2 C143.1 C144.2 C146.1 C147.1 C148.1 C149.1 C151.1 C152.1 C158.2 CN3.5 CN3.6 D25.2 D41.1 IC11.2 IC19.2 IC21.2 IC28.2 IC28.3 IC29.2 IC30.2 IC31.2 IC32.2 IC32.3 IC33.4 IC33.5 IC33.6 IC38.4 IC39.9 IC39.11 IC40.2 IC41.2 IC54.2 IC55.4 IC56.2 IC57.2 IC58.4 IC59.4 IC60.2 IC61.4 IC62.1 IC62.2 IC64.4 IC65.2 Q12.2 Q13.2 Q14.2 Q19.4 Q20.4 Q30.2 Q31.2 R55.1 R81.1 R83.1 R84.1 R172.1 R173.1 R188.1
VIN_A: IC36.1 IC44.3 IC47.7 R136.2
VIN_B: IC40.1 IC56.3 IC59.7 R161.2
DESAT_A: C89.2 D30.2 D31.2 IC51.2 Q22.3 R85.1 R87.2 R177.1 TP41.1
DESAT_B: C101.2 D38.2 D39.2 IC64.2 Q28.3 R105.1 R107.2 R182.1 TP42.1
FAULT_2_A: CN2.9 IC53.4
FAULT_2_B: CN3.9 IC65.4
GCLP_EN_A: IC25.1 IC27.2 IC46.3
GCLP_EN_B: IC31.1 IC33.2 IC58.3
IN2_N_A: CN2.8 IC7.1 R187.2
IN2_N_B: CN3.8 IC11.1 R188.2
PRED_EN_A: C155.1 IC35.6 IC44.1 IC46.6 IC47.6 IC49.6 IC49.7
PRED_EN_B: C158.1 IC39.6 IC56.1 IC58.6 IC59.6 IC61.6 IC61.7
SIG00009: Q11.2 R78.2
SIG00038: IC15.3
SIG00039: IC17.4
SIG00046: IC14.4 R28.1 R33.2
SIG00047: IC15.4 R30.1 R34.2
SIG00048: R30.2 R35.1
SIG00049: R31.1 R35.2
SIG00059: IC19.3
SIG00060: IC21.4
SIG00067: IC18.4 R49.1 R54.2
SIG00068: IC19.4 R51.1 R55.2
SIG00069: R51.2 R56.1
SIG00070: R52.1 R56.2
SIG00080: IC25.4 IC26.1
SIG00081: C77.2 IC25.3 R69.2
SIG00082: IC25.6 R69.1
SIG00083: IC26.4
SIG00084: D24.1 Q7.1 Q8.3 R65.1
SIG00085: Q7.2 R68.2
SIG00086: C75.2 IC24.3 R68.1 R73.2
SIG00087: IC24.1 R66.1 R71.2
SIG00088: IC24.4 R70.2
SIG00089: Q10.1 R70.1
SIG00090: C78.2 IC23.1 Q10.3 R67.1
SIG00091: IC23.4
SIG00092: IC23.6 IC27.1
SIG00093: IC27.3
SIG00094: IC22.1 IC27.7
SIG00095: IC22.3
SIG00096: IC22.4 R72.1
SIG00097: Q9.1 R72.2 R74.2 TP39.1
SIG00098: IC26.6 Q8.1
SIG00099: C87.2 IC31.3 R79.2
SIG00100: IC31.6 R79.1
SIG00101: IC31.4 IC32.1
SIG00102: IC32.4
SIG00103: IC32.6 Q12.1
SIG00104: D25.1 Q11.1 Q12.3 R75.1
SIG00106: C86.2 IC30.3 R78.1 R83.2
SIG00107: IC30.1 R76.1 R81.2
SIG00108: IC30.4 R80.2
SIG00109: Q14.1 R80.1
SIG00110: C88.2 IC28.1 Q14.3 R77.1
SIG00111: IC28.4
SIG00112: IC28.6 IC33.1
SIG00113: IC33.3
SIG00114: IC29.1 IC33.7
SIG00115: IC29.4 R82.1
SIG00116: IC29.3
SIG00117: Q13.1 R82.2 R84.2 TP40.1
SIG00118: IC34.6 IC36.4
SIG00119: IC34.2 IC36.3 IC36.6 R98.1
SIG00120: C99.2 IC37.1 R98.2
SIG00121: IC34.1 IC37.4
SIG00122: IC34.3 IC35.7 TP30.1
SIG00123: IC34.7 IC35.8 TP32.1
SIG00124: IC34.5 IC37.3 IC37.6
SIG00126: IC35.4 R90.1
SIG00127: C94.2 IC35.3
SIG00128: IC35.2
SIG00129: IC35.10 R103.1
SIG00130: Q16.3 R103.2
SIG00131: Q16.1 Q16.2 Q16.5 Q16.6 R93.1 R97.1 R99.1
SIG00132: Q15.3 R90.2
SIG00133: Q15.4 R88.1 R91.1 R92.1
SIG00134: Q17.3 R104.2
SIG00135: Q17.1 Q17.2 Q17.5 Q17.6 R100.1 R101.1 R102.1
SIG00136: R94.1 R95.1 R96.1 R100.2 R101.2 R102.2
SIG00137: R85.2 R86.1
SIG00138: D26.1 R86.2
SIG00139: D26.2 D27.1
SIG00140: D27.2 D28.1
SIG00141: D28.2 D29.1
SIG00142: IC38.2 IC40.3 IC40.6 R119.1
SIG00143: IC38.1 IC41.4
SIG00144: IC38.3 IC39.7 TP35.1
SIG00145: C111.2 IC41.1 R119.2
SIG00146: IC38.7 IC39.8 TP37.1
SIG00147: IC38.6 IC40.4
SIG00148: IC38.5 IC41.3 IC41.6
SIG00150: IC39.4 R110.1
SIG00151: C106.2 IC39.3
SIG00152: IC39.2
SIG00153: Q18.3 R110.2
SIG00154: Q18.4 R108.1 R111.1 R112.1
SIG00155: IC39.10 R123.1
SIG00156: Q19.3 R123.2
SIG00157: Q19.1 Q19.2 Q19.5 Q19.6 R113.1 R117.1 R118.1
SIG00158: Q20.3 R124.2
SIG00159: Q20.1 Q20.2 Q20.5 Q20.6 R120.1 R121.1 R122.1
SIG00160: R114.1 R115.1 R116.1 R120.2 R121.2 R122.2
SIG00161: R105.2 R106.1
SIG00162: D34.1 R106.2
SIG00163: D34.2 D35.1
SIG00164: D35.2 D36.1
SIG00165: D36.2 D37.1
SIG00167: Q22.1 R128.1 R178.2
SIG00168: R131.1 R133.2
SIG00169: Q24.1 R136.1
SIG00170: C120.2 IC51.3 R129.1 R132.2
SIG00171: Q23.1 R126.1 R179.2
SIG00173: D42.2 Q23.3 R135.2
SIG00174: Q25.1 R138.1
SIG00175: C121.2 D42.1 IC51.6 R127.1
SIG00176: C128.2 IC48.1 IC51.1 R137.1
SIG00177: IC51.7 R143.2
SIG00178: C129.2 IC42.1 R139.1 R143.1
SIG00179: R140.1 R142.2
SIG00180: C131.2 IC50.3 R142.1 R147.2
SIG00181: IC50.4 IC50.6 R146.2
SIG00182: IC50.5 R146.1 R149.2
SIG00183: IC48.4 IC49.5 TP46.1
SIG00184: IC50.8 R144.2
SIG00185: C132.2 IC45.1 R144.1
SIG00186: IC47.3 IC53.1
SIG00187: IC53.3
SIG00190: IC42.3 IC42.6 R138.2
SIG00190_2065554: IC11.3
SIG00191: IC42.4 IC46.1
SIG00192: IC45.3 IC45.6
SIG00193: IC48.3 IC48.6
SIG00194: IC45.4 IC46.2 IC49.1
SIG00195: IC43.2 IC43.3
SIG00196: IC43.5 IC46.7 TP45.1
SIG00197: IC49.2 IC49.3
SIG00198: IC44.4 IC46.5
SIG00199: IC43.6 IC43.7 IC47.1 IC47.5
SIG00200: IC51.5 R130.1 R134.2
SIG00203: Q28.1 R151.1 R183.2
SIG00204: R156.1 R158.2
SIG00205: Q30.1 R161.1
SIG00206: C140.2 IC64.3 R154.1 R157.2
SIG00208: Q29.1 R152.1 R184.2
SIG00209: D43.2 Q29.3 R160.2
SIG00210: C141.2 D43.1 IC64.6 R153.1
SIG00211: R150.1 R155.2
SIG00212: IC64.5 R155.1 R159.2
SIG00213: Q31.1 R163.1
SIG00215: C147.2 IC54.1 R164.1 R168.1
SIG00216: C151.2 IC62.3 R167.1 R172.2
SIG00217: R165.1 R167.2
SIG00218: IC62.4 IC62.6 R171.2
SIG00219: IC62.5 R171.1 R173.2
SIG00220: IC55.6 IC55.7 IC59.1 IC59.5
SIG00221: IC62.8 R169.2
SIG00222: C152.2 IC57.1 R169.1
SIG00223: IC59.3 IC65.1
SIG00224: IC65.3
SIG00227: IC54.3 IC54.6 R163.2
SIG00228: IC54.4 IC58.1
SIG00229: IC57.3 IC57.6
SIG00230: IC60.3 IC60.6
SIG00231: IC57.4 IC58.2 IC61.1
SIG00232: IC61.2 IC61.3
SIG00233: IC55.2 IC55.3
SIG00234: IC55.5 IC58.7 TP47.1
SIG00235: IC60.4 IC61.5 TP48.1
SIG00236: IC56.4 IC58.5
SIG00238: D29.2 P2.1
SIG00239: D37.2 P5.1
STO_VMOS_A: IC44.6 R104.1 TP43.1
STO_VMOS_B: IC56.6 R124.1 TP44.1
VE_A: C35.1 C37.1 C38.1 C47.2 C89.1 C90.1 C91.1 C92.2 C97.2 C98.2 C120.1 C121.1 C153.1 C154.1 C159.1 CN2.3 CN2.4 D30.1 D31.1 IC14.3 IC17.1 IC17.3 P4.1 Q22.2 Q23.2 R33.1 R87.1 R89.2 R132.1 R133.1 R134.1 R135.1
VE_B: C54.1 C56.1 C58.1 C66.2 C101.1 C102.1 C103.1 C104.2 C109.2 C110.2 C140.1 C141.1 C156.1 C157.1 C160.1 CN3.3 CN3.4 D38.1 D39.1 IC18.3 IC21.1 IC21.3 P8.1 Q28.2 Q29.2 R54.1 R107.1 R109.2 R157.1 R158.1 R159.1 R160.1
VGATE_A: C92.1 C94.1 D32.1 D33.2 IC35.5 P3.1 Q7.3 Q9.3 R65.2 R88.2 R89.1 R91.2 R92.2 R93.2 R94.2 R95.2 R96.2 R97.2 R99.2
VGATE_B: C104.1 C106.1 D40.1 D41.2 IC39.5 P7.1 Q11.3 Q13.3 R75.2 R108.2 R109.1 R111.2 R112.2 R113.2 R114.2 R115.2 R116.2 R117.2 R118.2
VGD_A: C40.2 C95.2 IC15.5 IC35.1 R31.2 TP12.1
VGD_B: C59.2 C107.2 IC19.5 IC39.1 R52.2 TP17.1
VL_A: C24.1 C48.2 C69.2 C70.2 C71.2 C72.2 C73.2 C74.2 C76.2 C93.2 C96.2 C100.2 C113.2 C114.1 C115.1 C117.2 C118.2 C119.1 C122.1 C123.2 C124.1 C126.2 CN2.7 IC7.5 IC17.5 IC22.5 IC23.5 IC24.5 IC25.5 IC26.5 IC27.8 IC34.8 IC36.5 IC37.5 IC42.5 IC43.8 IC44.5 IC45.5 IC46.8 IC47.8 IC48.5 IC49.8 IC50.7 IC53.5 R66.2 R67.2 R137.2 R139.2 R140.2 TP14.1
VL_B: C28.1 C67.2 C79.2 C80.2 C81.2 C82.2 C83.2 C84.2 C85.2 C105.2 C108.2 C112.2 C133.2 C134.1 C136.1 C137.2 C138.2 C139.1 C142.1 C143.2 C144.1 C146.2 CN3.7 IC11.5 IC21.5 IC28.5 IC29.5 IC30.5 IC31.5 IC32.5 IC33.8 IC38.8 IC40.5 IC41.5 IC54.5 IC55.8 IC56.5 IC57.5 IC58.8 IC59.8 IC60.5 IC61.8 IC62.7 IC65.5 R76.2 R77.2 R162.2 R164.2 R165.2 TP19.1
N03856: C35.2 C159.2 CN2.1 CN2.2 IC14.1 IC14.2
N03958: R27.1 R28.2
N502328: C54.2 C160.2 CN3.1 CN3.2 IC18.1 IC18.2
N505177: R48.1 R49.2
N855499: IC7.4 IC43.1 IC47.2
N855623: C116.1 Q21.2 Q21.5 R131.2
N855675: R125.1 R130.2
N871149: IC11.4 IC55.1 IC59.2
N871259: C135.1 Q27.2 Q27.5 R156.2
N872651: C149.2 IC60.1 IC64.1 R162.1
N1967382: Q21.3 R175.1
N1967396: Q21.1 R176.1
N1967438: Q21.4 R177.2
N1968040: Q25.3 R179.1
N1968066: Q24.3 R178.1
N1971632: Q27.3 R180.1
N1971644: Q27.1 R181.1
N1971690: Q27.4 R182.2
N1972235: Q31.3 R184.1
N1972365: Q30.3 R183.1
N1974780: IC64.7 R168.2
N2077882: CN3.10
N2078466: CN2.10
N2110725: IC7.3

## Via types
v1: diameter 0.8, hole 0.4, TOP to BOTTOM, 240 vias
v2: diameter 0.6, hole 0.3, TOP to BOTTOM, 61 vias

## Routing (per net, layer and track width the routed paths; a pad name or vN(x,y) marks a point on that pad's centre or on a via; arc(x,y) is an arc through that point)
VCC20_A: length 52.7
  TOP w0.5: R129.2 57.1,14.75 56.75,14.4 v1(54.4,14.4) ; R27.2 68.5,31.6 ; IC15.1 58.3,64.06 C39.2
  TOP w0.7: 62.2,63.6 61.45,64.35 C39.2
  TOP w0.8: 62.2,63.6 v1(63.85,61.95) v1(65.35,61.95) ; v1(74.85,41.5) v1(74.85,40)
  CONDUCTIVE3 w1: 55.9,13 55.9,6.9 ; 75.55,25 75.55,32.3
  BOTTOM w0.3: R125.2 67.25,9.3 v1(66.55,8.6) ; C127.2 62.4,8.03 62.62,8.25 63.4,8.25 63.77,7.88 IC51.8 ; R128.2 59.45,16.43 v1(58.5,17.38)
  BOTTOM w0.5: 54.4,13.7 v1(54.4,14.4) 55,15 R175.2 ; 54.4,13.7 54.4,13.03 55.02,12.4 ; 54.4,13.7 R176.2 ; C127.2 v1(62.4,6) ; v1(65.95,3.9) 66.35,3.5 R127.2 R126.2
  BOTTOM w0.8: v1(63.85,61.95) v1(65.35,61.95) 67.75,61.95 v1(70.55,59.15) v1(71.55,59.15)
  vias: v1(72.2,32.35) v1(72.2,31.05) v1(85.75,61.4) v1(85.75,60.4)
VCC20_B: length 34.9
  TOP w0.3: C135.2 31.8,56.42 R181.2
  TOP w0.5: C135.2 30.6,56.45 30.15,56 v1(29.25,56) ; R180.2 v1(38.55,55.3) ; R48.2 23.6,35.1
  TOP w1: 17.85,6.05 21.05,6.05
  TOP w1.5: 22.4,34.9 22.4,41.09
  CONDUCTIVE3 w1: 31.7,56.7 29.25,56.7
  BOTTOM w0.3: R152.2 38.65,49.2 39.35,49.9 39.35,52.75 38.15,53.95 R153.2 ; IC64.8 31.73,56.75 31.57,56.9 30.62,56.9 C148.2
  BOTTOM w0.5: R154.2 35.35,61.6 v1(35.65,61.9) 36.05,62.3 R151.2 ; v1(29.25,56) 29.73,56 C148.2 ; R153.2 37.7,54.45 v1(38.55,55.3) 38.55,56.35 R150.2
  vias: v1(15.5,4.9) v1(16.5,4.9) v1(21.6,44.5)
VEE_A: length 218.8
  TOP w0.2: 63.25,48.35 IC35.9 63.25,47.15 64.2,46.2 67.15,46.2 68.6,47.65 70.5,47.65
  TOP w0.3: R147.1 57.1,9.35 ; R147.1 56.55,10.15 ; R147.1 56.42,9.22 55.2,9.22 55.2,10.15 ; IC50.2 58.92,8.43 ; IC50.1 57.4,9.07 ; IC50.1 58.13,9.63 ; IC50.1 58.92,9.07 ; 59.62,9.95 C126.1 58.9,10.7
  TOP w0.5: v1(62.4,4.3) 61.81,4.2 R149.1 ; IC17.2 60.8,24.05 ; C47.1 62.34,24.49 ; C47.1 63.25,25.34 ; C47.1 64.16,24.49 ; 57.7,22.71 C48.1 58.61,23.56 ; R34.1 55.4,59.1 v1(54.95,59.55) ; v1(55.9,64.35) C39.1 57.35,64.11 IC15.2 57.35,61.95 57.75,61.55 59.35,61.55 C40.1 v1(61.25,62)
  TOP w0.8: v1(62.4,4.3) 62.95,4.3 64.45,2.8 70.05,2.8 C129.1 ; v1(67,40.85) 66.45,41.4 57.35,41.4 v1(56.4,42.35) ; v1(76.7,60.15) 77.4,60.85 v1(82.65,60.85) ; v1(69.85,7.95) 70.2,7.6 C132.1 71.95,7.6 v1(72.45,8.1)
  CONDUCTIVE3 w1: CN2.6 59,35.23 ; CN2.6 59.02,32.75 ; CN2.6 CN2.5 ; 73.2,19 73.2,21.9
  BOTTOM w0.2: IC23.2 68.15,49.5 68.4,49.25 68.4,47.83 C70.1 ; IC22.2 71.3,53.15 71.15,53 71.15,52.12 C72.1 ; IC44.2 62.8,17.45 62.65,17.6 61.27,17.6 61.05,17.38 C115.2 ; IC24.2 64.85,42.1 64.65,41.9 64.65,40.58 C74.1 ; IC53.2 61.3,31.35 61.15,31.2 61.15,29.9 C124.2 ; IC26.2 72.7,37.41 72.61,37.5 71.42,37.5 70.8,36.88 C69.1 ; IC7.2 62.5,26.4 62.62,26.52 C24.2
  BOTTOM w0.3: IC34.4 57.35,45.3 ; IC43.4 62.55,23.85 62.3,23.6 60.08,23.6 C113.1 ; 66.95,50.15 IC23.3 67.7,50.65 ; 68.72,30.2 68.9,30.38 68.9,32.1 68.75,32.25 IC25.2 67.55,32.25 66.7,33.1 C77.1 ; C96.1 53.5,49.02 53.5,47.9 53.8,47.6 IC36.2 ; 59.08,49.55 58.9,49.38 58.9,47.9 59.2,47.6 IC37.2 ; 57.65,25.15 IC47.4 58.15,24.45 ; v1(68.85,26.1) 68.6,25.55 68.6,25.02 68.92,24.7 71,24.7 71.25,24.95 IC49.4 ; IC51.4 65.72,9.28 65.3,8.85 62.62,8.85 62.4,9.07 62.4,9.22 ; v1(63.25,25.65) 63.7,25.2 C117.1 63.83,24.48 64.6,23.7 66.2,23.7 66.35,23.85 IC46.4 ; IC42.2 70.75,16 ; IC48.2 71.1,12.85 70.72,13.22 70.72,13.93 71.1,14.3 72.12,14.3 72.42,14.6 C122.2 ; 68.9,52.2 IC27.4 68.4,51.5 ; IC26.2 72.7,35.9 72.55,35.75 72.3,35.75 72.05,36 IC26.3 ; C24.2 63.58,29.3 R187.1 ; IC27.5 68.9,53.4 ; IC45.2 66.95,15.9 ; C78.1 66.92,50.3 ; v1(62,49) 62.42,48.58 Q10.2 ; IC23.2 66.95,49.5 ; IC27.6 69.4,53.4
  BOTTOM w0.5: C78.1 64.95,50.3 ; C96.1 54.48,50.83 55.65,52 58.02,52 v1(59.33,50.7) ; 67.85,55.55 C73.1 68.97,56.65 ; C74.1 66.3,40.15 v1(67,40.85) 68.35,39.5 68.35,37.58 69.05,36.88 C69.1 ; C113.1 59.73,23.77 v1(58.7,22.75) ; v1(76.7,60.15) R74.1 76.95,54.4 Q9.2 ; C99.1 59.89,50.9 v1(59.33,50.7) ; v1(59.67,30.32) 60.25,29.75 C124.2 ; Q24.2 v1(57,17.4) ; Q17.4 82.35,61.15 v1(82.65,60.85) ; C72.1 71.62,50.27 C71.1 71.65,49.4 v1(70.8,48.55) ; v1(59.33,50.7) 59.08,50.15 59.08,49.55 ; 62.4,9.22 v1(62.4,10.4) ; v1(69.85,7.95) 70.25,8.35 C128.1 ; v1(76.8,42.6) 76.23,42.8 D24.2 ; v1(71.2,40.85) 71.73,40.57 Q8.2 ; 57.52,43.4 57.52,42.55 57.33,42.35 v1(56.4,42.35) ; C114.2 68.85,16.4 ; v1(68.95,27.9) 68.72,28.46 68.72,30.2 ; C115.2 60.52,17.38 v1(59.9,18) ; C75.1 66,43.45 R71.1 ; C75.1 66.8,44.25 ; C75.1 R73.1 68.15,44.2 ; R187.1 64.3,31.5 v1(61.6,34.2) ; v1(72.45,8.1) 72.2,7.55 Q25.2 ; C122.2 72.42,17.52 v1(72.1,17.85) ; C119.2 64.9,17.12 64.9,16.05 ; v1(66.65,47.35) 67.25,47.4 C70.1
  BOTTOM w0.8: v1(61.25,62) 57.4,62 v1(54.95,59.55)
  BOTTOM w1: v1(62.4,4.3) 61,5.7 61,7.65 v1(60.05,8.6)
  vias: v1(54.95,26.95) v1(57.5,11.2) v1(57.5,10.1) v1(63.5,49) v1(64.25,56.85) v1(64.25,55.35) v1(65.55,14.9) v1(65.65,47.35) v1(68.35,14.25) v1(69.65,14.25) v1(70.55,43.85) v1(71.55,43.85) v1(82.65,59.8)
VEE_B: length 165.8
  TOP w0.2: 27.4,18.55 29.5,18.55 31.05,20.1 33.55,20.1 34.35,19.3 34.5,19.3 34.75,19.05 IC39.9 34.75,17.95 ; C144.2 29.75,37.55 31.2,37.55 31.35,37.7 IC65.2
  TOP w0.3: 33.35,50.9 33.52,51.08 34.27,51.08 ; 38.35,47.85 R172.1 37.65,48.5 ; C146.1 27.85,52.38 ; IC62.1 33.48,50.42 ; IC62.1 35.06,50.42 ; IC62.1 34.27,49.87 ; 28.95,54.6 R173.1 28.1,53.8 ; C151.1 36.23,48.88 35.65,49.45 ; C151.1 37.4,48.88 ; C151.1 36.65,48.15 ; IC40.2 30.07,23.25 ; C139.2 33.65,44.83 33.65,43.3 33.4,43.05 IC57.2
  TOP w0.5: C59.1 v1(35.5,8.25) ; 19.3,37.61 C67.1 20.21,38.46 ; v1(23.35,22.8) 25.25,22.8 26.09,21.96 v1(26.3,21.4) ; C144.2 28.55,37.4 v1(27.5,36.35) ; C66.1 16.54,35.66 ; C66.1 16.54,37.49 ; C66.1 17.39,36.57 ; 35.05,49.45 C152.1 35.85,48.25 36.1,48 ; C139.2 32.2,46.28 v1(31.9,46.8) ; IC21.2 16.25,39.15 ; v1(38.5,4.9) R55.1 36.95,5.3 35.25,5.3 34.9,4.95 IC19.2 34.9,3.05 34.61,2.76 C57.1 v1(31,2.76)
  CONDUCTIVE3 w1: CN3.5 35.23,32.95 ; CN3.5 CN3.6 ; CN3.5 34.1,34 ; CN3.6 37.77,35.05 ; CN3.6 38.9,34 ; CN3.6 37.77,32.95
  BOTTOM w0.2: IC11.2 30.2,33.7 29.9,33.4 R188.1 ; IC29.2 17.45,25.95
  BOTTOM w0.3: IC55.4 28.65,37.95 28.85,38.15 31.07,38.15 C133.1 ; C86.1 23.5,34 R83.1 ; 13.2,24.4 14.18,24.4 14.18,25.68 C81.1 ; C112.1 31.12,24.82 30.77,24.48 30.27,24.48 30.1,24.3 30.1,23.45 30.3,23.25 IC40.2 ; R83.1 22.7,35.25 ; R83.1 23.5,36.2 ; C85.1 19.5,29.6 ; C85.1 20.23,30.3 ; C85.1 20.23,28.75 ; C87.1 22.8,36.3 ; C87.1 21.9,37.25 ; C87.1 20.95,36.3 v1(20.55,36.7) ; C138.1 36.7,43.12 ; 15.75,34.7 16.48,34.7 16.4,34.62 IC28.3 15.65,33.45 ; IC32.2 24.35,30.8 ; Q13.2 19.95,20.35 ; Q13.2 19.15,21.2 ; Q13.2 18.35,20.35 ; 30.35,57.98 30.68,57.65 33.36,57.65 33.67,57.97 IC64.4 ; IC58.4 29.5,48.4 29.85,48.75 31.98,48.75 C137.1 31.9,48.33 v1(31.9,46.8) ; 21.95,24 22.1,24.15 Q12.2 22.9,24.95 ; C81.1 14.15,26.7 ; C81.1 13.25,25.7 ; 17.6,28.95 IC33.6 17.6,27.55 ; 18.1,30.25 IC33.4 18.6,30.95 ; 18.45,21.9 R84.1 17.8,21.2 ; C136.2 35.77,49.05 34.35,49.05 34.1,48.8 IC56.2 ; IC59.4 33.15,41.75 ; 16.85,36.25 Q14.2 16.23,35.65 ; IC61.4 28.7,43 29.2,43.5 31.12,43.5 31.4,43.23 C143.1 v1(31.4,41.95) ; 18.1,28.95 IC33.5 18.1,27.55 ; IC54.2 26.4,51.05 ; 26.25,31 C79.1 26.02,30.05 IC32.3 25,30.8 ; IC30.2 25.55,37.02 26,37.48 C84.1 ; IC28.2 15.65,32.8 ; IC38.4 36.95,22.35 ; D25.2 22.4,23.6 ; IC31.2 20.9,31.5 ; IC60.2 26.7,41.9
  BOTTOM w0.5: v1(31.05,36.8) 31.35,37.1 C133.1 ; C134.2 27.3,50.77 ; C112.1 v1(31.12,26.5) ; v1(31.12,26.5) v1(31.12,28.3) 31.12,31.57 R188.1 ; v1(31.12,26.5) 29.7,26.5 C111.1 ; D41.1 C110.1 13.18,21.38 v1(13.35,21.95) ; Q30.2 36.55,64.3 v1(34.85,64.3) ; C84.1 v1(27.5,36.35) 27.7,35.78 R81.1 ; 14.45,28.68 C82.1 15.45,29.65 ; v1(37.9,25.3) 36.98,25.3 C105.1 36.77,24.25 ; C28.2 v1(32.9,34.12) ; 26.65,53.15 C147.1 27.65,52.37 v1(27.45,51.8) ; v1(23.35,22.8) 22.75,22.75 D25.2 ; C136.2 36,48.07 v1(36.2,47.3) 36.85,46.65 Q31.2 ; 12.45,32.45 C88.1 13.3,31.3 ; C149.1 29.7,59.2 29.25,58.75 v1(29.25,58.3) 29.57,57.98 30.35,57.98 ; C86.1 23.35,32.65 ; C142.2 v1(24.75,41.95)
  vias: v1(14.15,30.6) v1(14.15,27.65) v1(14.65,21.95) v1(15.2,35.4) v1(17.55,29.65) v1(17.95,26.75) v1(18.4,35.9) v1(18.85,4.85) v1(19.85,4.85) v1(20.55,35.7) v1(24.85,32.6) v1(27.3,21.4) v1(30.3,20.4) v1(31.35,18.95) v1(32.35,18.95) v1(34.5,17.3) v1(36,17.3) v1(37.1,42.55) v1(38.15,15.25)
VIN_A: length 41.8
  BOTTOM w0.15: 57.1,20.3 57.2,20.4 ; 57.1,20.3 56.85,20.05 55.82,20.05 55.14,20.73 54.5,20.73 53.45,21.78 53.45,39.7 55.02,41.27 55.02,41.91 53.45,43.48 53.45,46.7 53.7,46.95 IC36.1 ; 57.1,20.3 57.1,20.5 ; 57.2,20.4 59.05,20.4 59.15,20.3 R136.2 59.15,19.65 59.2,19.6 59.2,17.7 60.23,16.68 61.52,16.68 61.75,16.9 IC44.3 ; 57.2,20.4 57.1,20.5 ; 57.1,20.5 56.65,20.95 IC47.7
VIN_B: length 57.1
  TOP w0.15: v2(36.15,41.4) 38.05,41.4 v2(38.6,40.85) 39.8,39.65 39.8,27.4 39.33,26.93 37.98,26.93 36.5,25.45 32.9,25.45 31.35,23.9 IC40.1
  BOTTOM w0.15: IC56.3 33.55,48.2 33.55,47.79 34.02,47.32 34.02,45.98 34.15,45.85 IC59.7 34.15,44.1 35.1,43.15 35.1,42.65 35.95,41.8 v2(36.15,41.4) ; R161.2 40.1,59.85 40.1,42.35 v2(38.6,40.85)
DESAT_A: length 25.6
  TOP w0.5: R85.1 69.8,15.7 D31.2 69.6,15.7 D30.2 C89.2 R87.2 65.9,13.15 TP41.1 67.45,11.6 v2(68.8,11.6)
  BOTTOM w0.3: v2(68.8,11.6) 67.33,11.6 Q22.3 66.28,12.07 65.65,12.7 R177.1 63.85,11.85 64.42,11.28 IC51.2
DESAT_B: length 23.5
  TOP w0.5: R105.1 35.75,63.5 D39.2 37.7,63.1 38.2,62.6 D38.2 38.3,62.5 38.35,62.45 C101.2 38.05,60 37.5,60.55 R182.1 34.69,60.55 v2(34.25,60.65) 33.4,61.5 30,61.5 TP42.1
  BOTTOM w0.3: v2(34.25,60.65) 33.83,60.5 R107.2 33.12,60.33 Q28.3 31.7,59.9 32.38,59.23 IC64.2
FAULT_2_A: length 11.8
  BOTTOM w0.15: CN2.9 56.55,37.76 56.55,36.1 57.6,35.05 58.3,35.05 60.05,33.3 61.77,33.3 62.52,32.55 IC53.4
FAULT_2_B: length 3.7
  TOP w0.15: IC65.4 32.33,38.92 32.5,38.75 34.31,38.75 CN3.9
GCLP_EN_A: length 41
  BOTTOM w0.15: 66,31 65.9,31.1 ; 66,31 66.1,31.1 ; 66,31 66,26.05 65.85,25.9 IC46.3 ; 65.9,31.1 65.4,31.6 65.4,31.85 61.8,35.45 61.55,35.45 60.4,36.6 60.4,40.45 62,42.05 62,46.15 61.8,46.35 61.8,48.15 61.3,48.65 61.3,49.4 61.85,49.95 63.9,49.95 64.97,51.02 68.17,51.02 68.4,50.8 69.8,50.8 69.9,50.9 IC27.2 ; 65.9,31.1 66.1,31.1 ; 66.1,31.1 66.6,31.6 IC25.1
GCLP_EN_B: length 27
  TOP w0.15: v2(24.75,40.1) 25.4,40.1 29.05,43.75 v2(29.05,46.85)
  BOTTOM w0.15: IC58.3 30,47.4 29.45,46.85 v2(29.05,46.85) ; 19.35,31.5 19.35,31.1 19.6,30.85 IC31.1 ; 19.35,31.5 19.25,31.6 ; 19.35,31.5 19.35,31.6 ; 19.25,31.6 17.3,31.6 17.1,31.4 IC33.2 ; 19.25,31.6 19.35,31.7 ; 19.25,31.6 19.35,31.6 ; 19.35,31.7 19.35,32.65 19.8,33.1 19.8,37.2 22.7,40.1 v2(24.75,40.1) ; 19.35,31.7 19.35,31.6
IN2_N_A: length 16.8
  TOP w0.15: v2(61.95,27.5) v2(63.35,27.5)
  BOTTOM w0.15: v2(63.35,27.5) 64,27.5 R187.2 65.15,28.65 65.15,30 64.88,30.27 64.88,31.87 61.82,34.93 59.38,34.93 CN2.8 ; IC7.1 62.02,27.06 v2(61.95,27.5)
IN2_N_B: length 9.8
  BOTTOM w0.15: CN3.8 36.53,35.3 35,35.3 32.5,32.8 R188.2 30.55,33.65 IC11.1
PRED_EN_A: length 81.9
  TOP w0.15: IC35.6 58.85,47.6 58.48,47.98 C155.1 57.12,49.85 56.65,49.85 55.5,51 55.5,52.55 v2(54.95,53.1) ; v2(68.8,21.4) 66.05,21.4 v2(64.45,19.8) 63.92,20.32 62.77,20.32 62.25,19.8 v2(61.8,19.8) ; v2(56.7,22.7) 56.5,22.3 55.2,21 55.2,18.6 v2(54.3,17.7)
  BOTTOM w0.15: IC44.1 63.45,17.15 64.15,17.85 64.15,19.5 v2(64.45,19.8) ; v2(54.3,17.7) 52.05,19.95 52.05,50.75 54.4,53.1 v2(54.95,53.1) ; v2(68.8,21.4) 69.65,21.4 70.25,22 IC49.7 70.25,23.41 70.39,23.55 70.6,23.55 70.75,23.4 IC49.6 ; v2(56.7,22.7) 57.15,22.25 IC47.6 57.15,21.35 57.77,20.73 59.2,20.73 59.55,20.38 61.23,20.38 v2(61.8,19.8) 62.1,19.8 62.98,20.68 65.44,20.68 65.85,21.08 IC46.6
PRED_EN_B: length 56.5
  TOP w0.15: v2(33.5,46.1) v2(34.85,46.1) 35.26,46.27 36.16,46.27 36.55,45.88 36.55,45 37.6,43.95 38.9,43.95 40.75,42.1 40.75,20.25 38.98,18.48 C158.1 37.92,18.7 IC39.6 ; v2(28.05,46.85) 28.05,44.22 v2(27.9,43.8)
  BOTTOM w0.15: IC61.7 29.7,45.85 ; 29.7,45.85 29.82,45.98 ; 29.7,45.85 29.7,45.98 ; 29.7,45.85 29.57,45.98 ; v2(34.85,46.1) 34.33,46.62 34.33,47.33 34.75,47.75 IC56.1 ; 29.82,45.98 30.82,45.98 31,46.15 33.05,46.15 v2(33.5,46.1) 33.65,45.68 IC59.6 ; 29.82,45.98 29.7,45.98 ; 29.7,45.98 29.57,45.98 ; 29.57,45.98 29.43,45.98 29.2,45.75 IC61.6 29.2,44.3 28.7,43.8 v2(27.9,43.8) ; v2(28.05,46.85) 29,47.8 29,49.2 30,50.2 IC58.6
SIG00009: length 1.4
  BOTTOM w0.15: Q11.2 23.32,20.65 R78.2
SIG00046: length 3.2
  TOP w0.5: IC14.4 67.2,33.67 R33.2 R28.1
SIG00047: length 3.3
  TOP w0.5: IC15.4 56.4,58.8 R34.2 R30.1
SIG00048: length 1.3
  TOP w0.5: R35.1 R30.2
SIG00049: length 1.1
  TOP w0.5: R31.1 R35.2
SIG00067: length 3.8
  TOP w0.5: R49.1 R54.2 25.95,32.15 24.58,30.78 IC18.4
SIG00068: length 3.6
  TOP w0.5: R51.1 37.35,7.4 R55.2 36.25,6.4 IC19.4
SIG00069: length 1.3
  TOP w0.5: R51.2 R56.1
SIG00070: length 1.1
  TOP w0.5: R56.2 R52.1
SIG00080: length 5.8
  BOTTOM w0.15: IC26.1 73.35,35.25 71,32.9 IC25.4
SIG00081: length 4.9
  BOTTOM w0.15: C77.2 67.45,35.65 68.15,34.95 R69.2 68.95,33.35 68.95,33 68.85,32.9 IC25.3
SIG00082: length 3.3
  BOTTOM w0.15: R69.1 69.3,33.8 69.3,31.85 69.55,31.6 IC25.6
SIG00084: length 7.2
  BOTTOM w0.15: Q7.1 75.42,45.42 R65.1 75.5,44.55 74.85,43.9 73.35,43.9 72.9,43.45 D24.1 Q8.3
SIG00085: length 4.5
  BOTTOM w0.15: R68.2 70.95,42.05 73.5,44.6 Q7.2
SIG00086: length 4.3
  BOTTOM w0.15: IC24.3 66.3,41.45 C75.2 R73.2 R68.1
SIG00087: length 3.6
  BOTTOM w0.15: IC24.1 64.65,42.75 63.9,43.5 R71.2 R66.1
SIG00088: length 3.2
  BOTTOM w0.15: R70.2 62.8,43.25 62.6,43.05 62.6,41.7 62.85,41.45 IC24.4
